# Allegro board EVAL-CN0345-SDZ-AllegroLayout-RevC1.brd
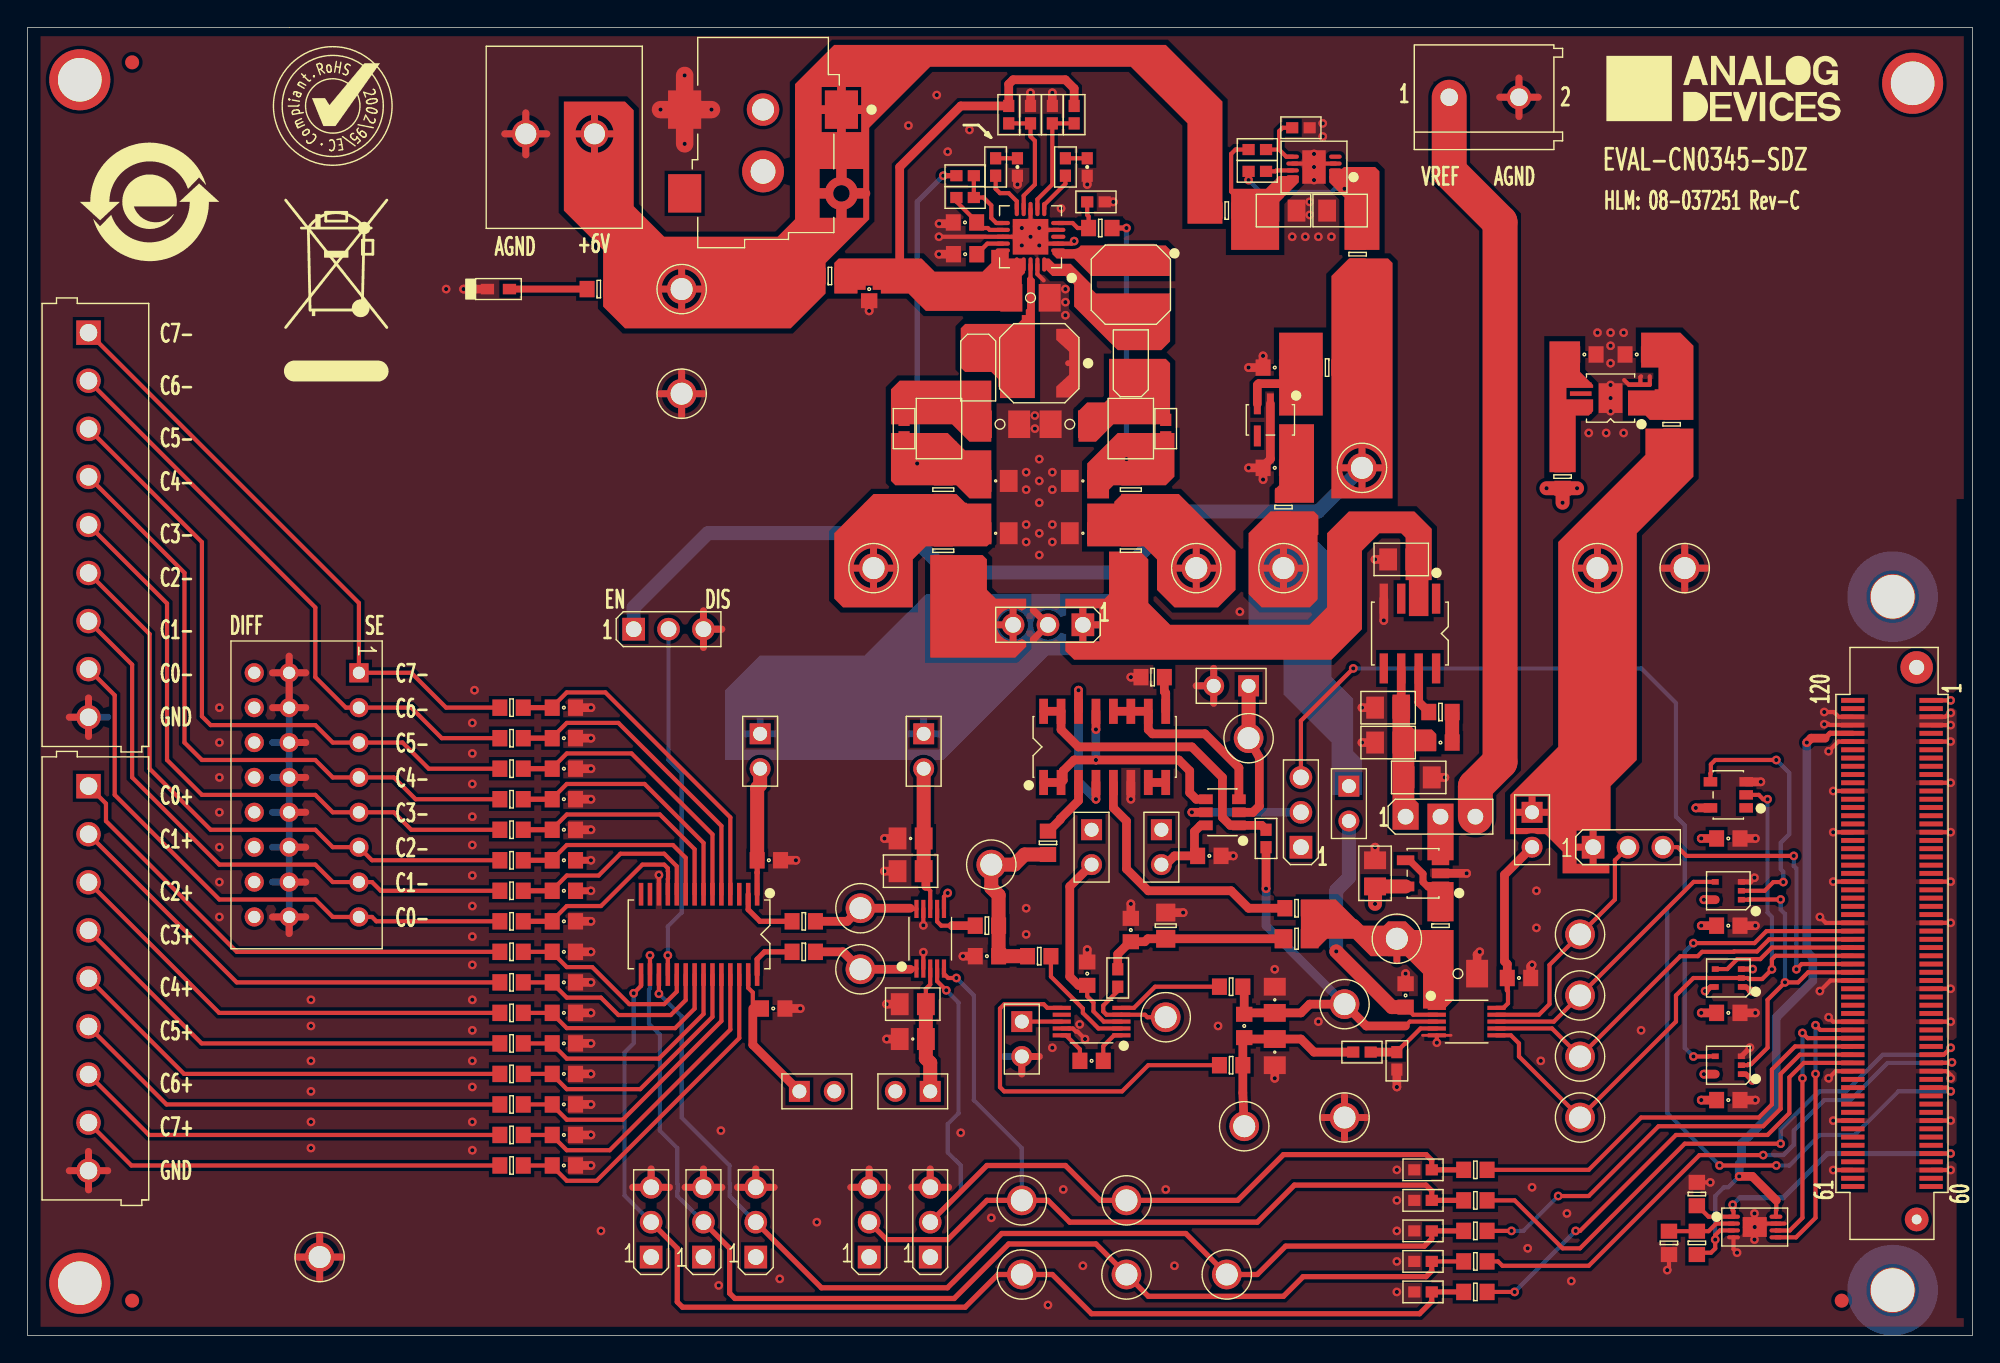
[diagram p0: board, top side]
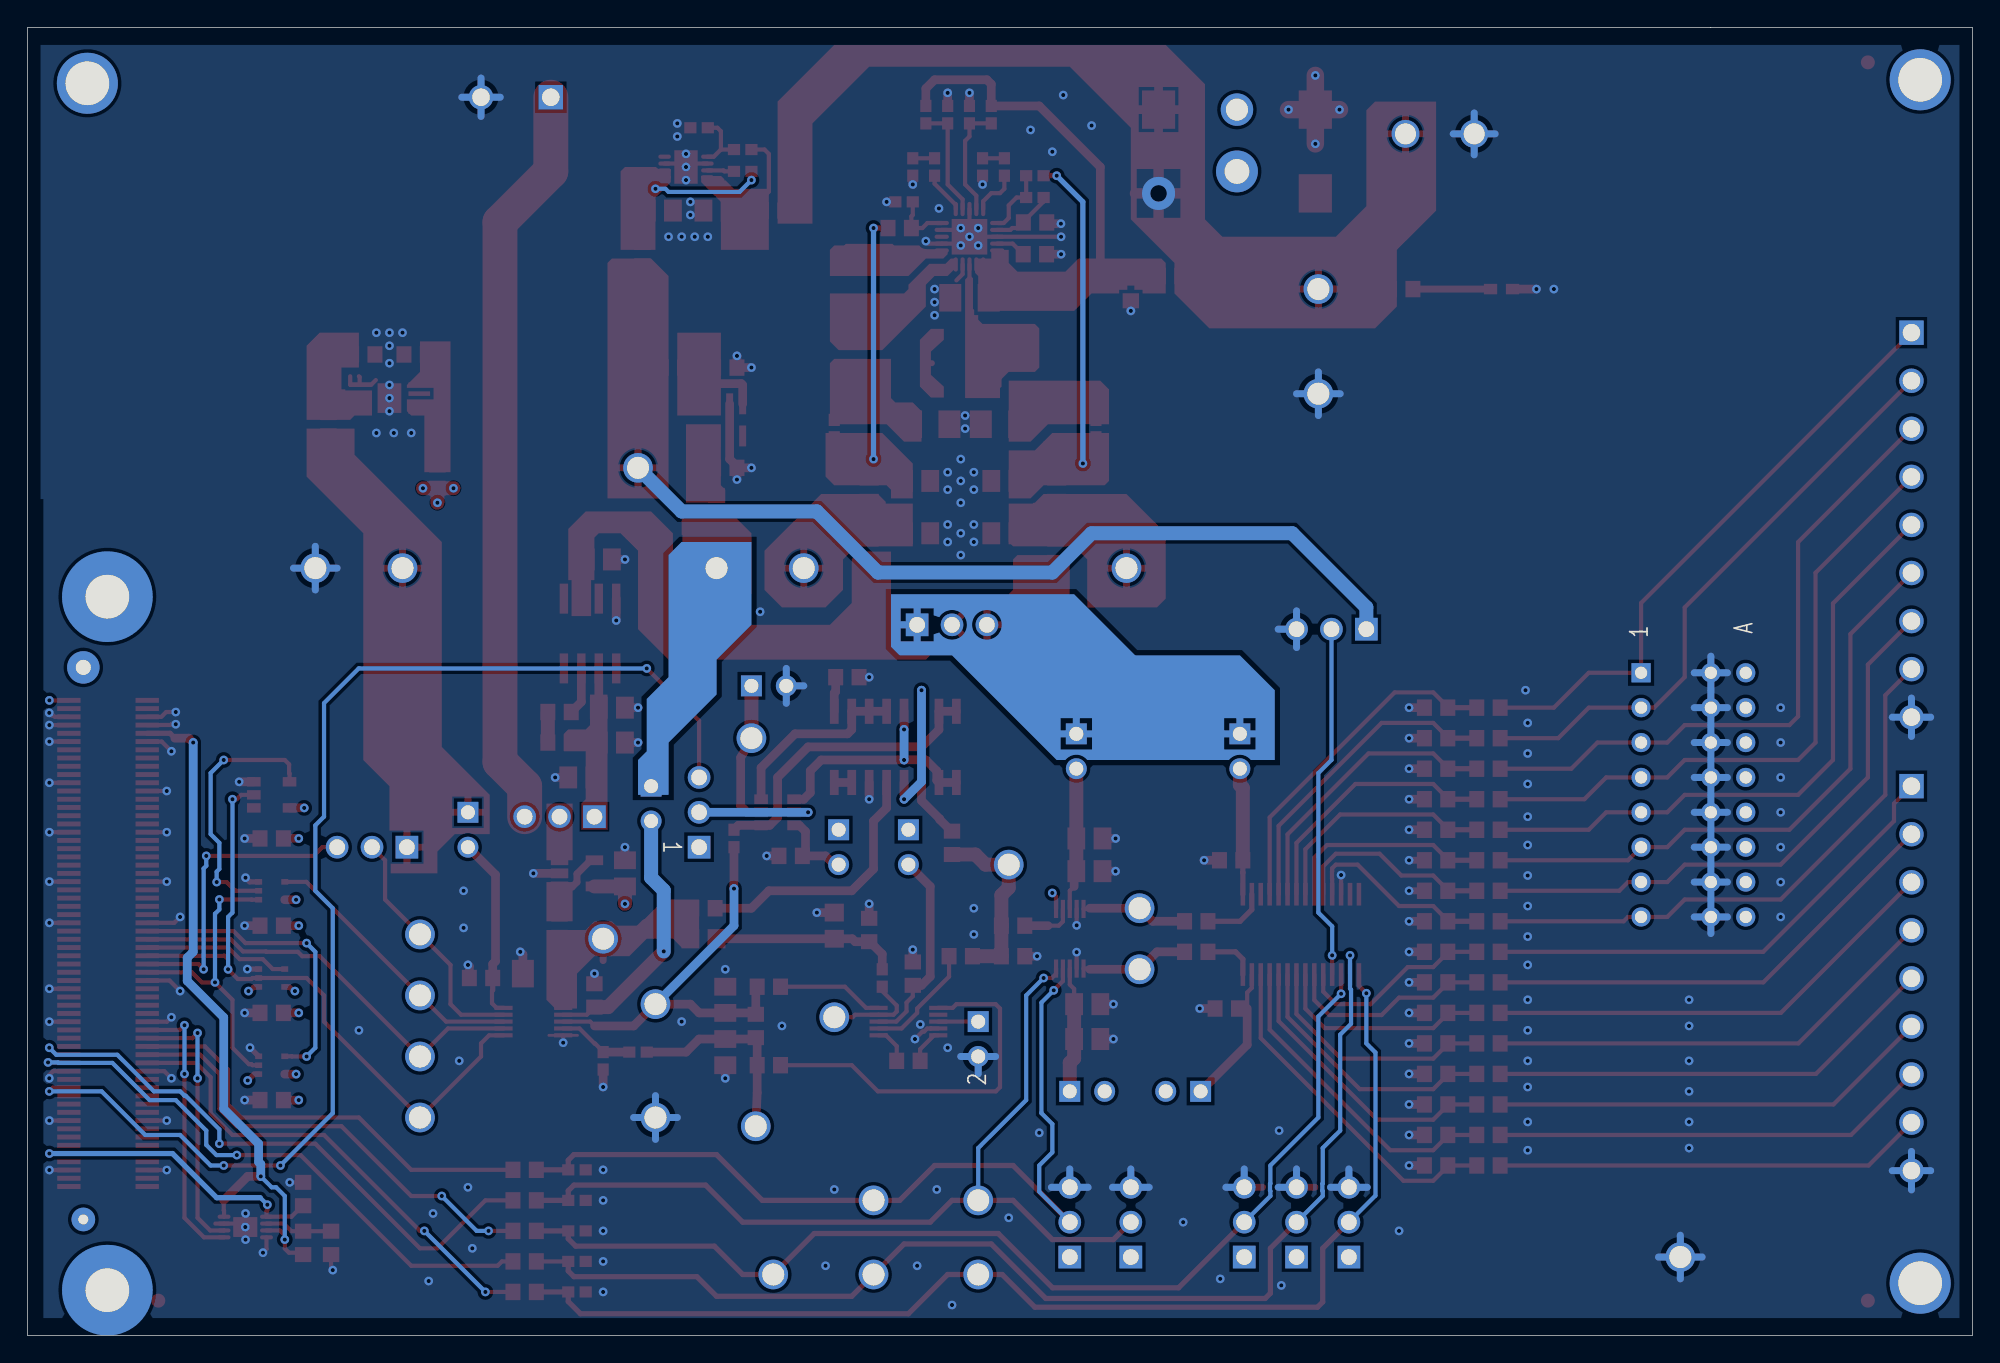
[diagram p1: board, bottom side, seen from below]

Outline 141.61 x 95.25 mm; copper layers: TOP, L2_GND, L3_POWER, BOTTOM. Coordinates in mm from the lower left corner of the outline.
Outline path: 0,95.25 19.05,95.25 141.61,95.25 141.61,0 0,0 0,95.25

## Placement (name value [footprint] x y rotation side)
C1  2700pF  [C0603]  39.05 45.72 180 top
C2  2700pF  [C0603]  39.05 43.5 180 top
C3  2700pF  [C0603]  39.05 41.27 180 top
C4  2700pF  [C0603]  39.05 39.05 180 top
C5  2700pF  [C0603]  39.05 36.83 180 top
C6  2700pF  [C0603]  39.05 34.61 180 top
C7  2700pF  [C0603]  39.05 32.38 180 top
C8  2700pF  [C0603]  39.05 30.16 180 top
C9  2700pF  [C0603]  39.05 27.94 180 top
C10  2700pF  [C0603]  39.05 25.72 180 top
C11  2700pF  [C0603]  39.05 23.49 180 top
C12  2700pF  [C0603]  39.05 21.27 180 top
C13  2700pF  [C0603]  39.05 19.05 180 top
C14  2700pF  [C0603]  39.05 16.83 180 top
C15  2700pF  [C0603]  39.05 14.61 180 top
C16  2700pF  [C0603]  39.05 12.38 180 top
C17  0.1UF  [C0603]  54.29 23.81 0 top
C18  0.1UF  [C0603]  53.98 34.61 0 top
C19  0.1uF  [C0805H53]  64.29 33.81 0 top
C20  10uF  [C0805H60]  64.29 36.2 0 top
C21  0.1UF  [C0603]  86.04 34.92 0 top
C22  10uF  [C0805H60]  64.45 21.59 180 top
C23  0.1uF  [C0805H53]  64.45 24.13 180 top
C24  2700pF  [C0603]  69.85 27.62 0 top
C25  2700pF  [C0603]  77.47 20 0 top
C26  0.1UF  [C0603]  77.15 26.35 270 top
C27  0.1uF  [C0603]  80.33 29.53 270 top
C28  1200pF  [C0805]  90.81 24.45 90 top
C29  1200pF  [C0805]  90.81 20.64 90 top
C30  1000PF  [C0603]  88.58 22.54 90 top
C31  10uF  [C1206H71]  104.14 26.35 180 top
C32  0.1UF  [C0603]  100.33 24.77 270 top
C33  0.1UF  [C0603]  108.59 26.04 0 top
C34  0.1uF  [C0805H53]  100.01 56.52 0 top
C35  22uF  [C0603]  61.28 76.2 90 top
C36  1uF  [C0603]  68.26 78.74 0 top
C37  10000pF  [C0603]  102.87 43.18 180 top
C38  10uF  [C1206H71]  73.03 75.57 180 top
C39  0.1uF  [C0805H53]  99.06 45.72 0 top
C40  1UF  [C0805H53]  99.06 43.18 0 top
C41  1UF  [C0805H53]  91.44 81.92 180 top
C42  0.1uF  [C0805H53]  101.28 40.64 180 top
C43  1uF  [C1206H71]  70.8 66.36 180 top
C44  1uF  [C1206H71]  75.88 66.36 0 top
C45  0.1uF  [C0805H53]  98.11 33.66 90 top
C46  6800pF  [C0402]  77.15 85.09 270 top
C47  39000pF  [C0402]  72.07 85.09 270 top
C48  1uF  [C0603]  68.25 81.05 180 top
C49  10uF  [C0805H60]  70.49 62.23 0 top
C50  10uF  [C0805H60]  76.84 62.23 0 top
C51  1UF  [C0805H53]  95.57 81.92 0 top
C52  10uF  [C0805H60]  76.84 58.42 0 top
C53  10uF  [C0805H60]  70.49 58.42 180 top
C54  1UF  [C0603]  90.81 70.48 0 top
C55  1UF  [C0603]  113.35 71.44 180 top
C56  1UF  [C0603]  90.81 63.18 0 top
C57  1UF  [C0603]  117.16 71.44 0 top
C58  0.1uF  [C0603]  123.83 29.84 180 top
C59  0.1uF  [C0603]  123.83 17.14 180 top
C60  0.1uF  [C0603]  123.83 36.2 180 top
C61  0.1uF  [C0603]  123.83 23.49 180 top
CNV  WHT  [CNLOOPTP]  113.03 15.88 0 top
D1  DFLS240-7  [DSML110W70H39]  80.33 70.8 90 top
D2  DFLS240-7  [DSML110W70H39]  69.22 70.48 270 top
DRV_IN  WHT  [CNLOOPTP]  70.17 34.29 0 top
GND1  BLK  [CNLOOPTP]  95.89 15.88 0 top
GND2  BLK  [CNLOOPTP]  120.65 55.88 0 top
GND3  BLK  [CNLOOPTP]  47.63 68.58 0 top
GND4  BLK  [CNLOOPTP]  21.27 5.71 0 top
IN+  WHT  [CNLOOPTP]  95.89 24.13 0 top
IN-  WHT  [CNLOOPTP]  88.58 15.24 0 top
L1  22uH  [LSMSQ189H123]  73.66 70.8 180 top
L2  22uH  [LSMSQ189H123]  80.33 76.52 270 top
L3  0.68uH  [LSML126W90H59]  66.36 66.04 270 top
L4  0.68uH  [LSML126W90H59]  80.33 66.04 270 top
MUX_0  WHT  [CNLOOPTP]  87.31 4.45 0 top
MUX_1  WHT  [CNLOOPTP]  80.01 4.45 0 top
MUX_2  WHT  [CNLOOPTP]  72.39 4.45 0 top
NOREF  -  []  -164.4 -183.78 0 top
NOREF#2  -  []  65.11 108.96 0 top
NOREF#3  -  []  -165.67 -185.05 0 top
NOREF#4  -  [unnamed#2]  7.62 92.71 180 top
NOREF#5  -  []  31.75 86.36 0 top
NOREF#6  -  []  123.51 90.81 0 top
NOREF#7  -  []  33.66 0 0 top
NOREF#8  -  [unnamed#2]  3.81 91.44 270 top
NOREF#9  -  [unnamed#2]  3.81 3.81 270 top
NOREF#10  -  []  141.69 76.2 180 top
NOREF#11  -  []  8.89 82.55 0 top
NOREF#12  -  [unnamed#2]  132.08 2.54 180 top
NOREF#13  -  []  -156.78 -174.63 0 top
NOREF#14  -  []  53.47 94.52 0 top
NOREF#15  -  []  208.75 320.17 0 top
NOREF#16  -  []  141.69 0 90 top
NOREF#17  -  []  33.66 76.2 270 top
NOREF#18  -  []  22.23 89.54 0 top
NOREF#19  -  [unnamed#2]  137.24 91.19 270 top
NOREF#20  -  []  174.97 92.45 0 top
NOREF#21  -  [unnamed#2]  7.62 2.54 180 top
NOREF#22  -  []  141.61 0 90 top
NOREF#23  -  []  10.16 307.34 0 top
NOREF#24  -  []  0 0 0 top
P1  CTB3051/9  [CNCELCTB3051_9]  4.45 73.03 270 top
P2  SAMTECTSW10608GS3PIN  [CNBERG1X3H205LD36]  100.33 37.78 0 top
P3  KRM2 02  [CNTERM_2P]  103.51 90.17 0 top
P4  SAMTECTSW10608GS3PIN  [CNBERG1X3H205LD36]  45.4 5.71 90 top
P5  SAMTECTSW10608GS3PIN  [CNBERG1X3H205LD36]  49.21 5.71 90 top
P6  SAMTECTSW10608GS3PIN  [CNBERG1X3H205LD36]  53.02 5.71 90 top
P7  69157-102  [CNBERG69157-102]  56.2 17.78 0 top
P8  69157-102  [CNBERG69157-102]  53.34 43.81 270 top
P9  SAMTECTSW10608GS3PIN  [CNBERG1X3H205LD36]  61.28 5.71 90 top
P10  SAMTECTSW10608GS3PIN  [CNBERG1X3H205LD36]  65.72 5.71 90 top
P11  69157-102  [CNBERG69157-102]  82.55 36.83 270 top
P12  69157-102  [CNBERG69157-102]  65.72 17.78 180 top
P13  69157-102  [CNBERG69157-102]  65.25 43.81 270 top
P14  69157-102  [CNBERG69157-102]  88.9 47.31 180 top
P15  69157-102  [CNBERG69157-102]  77.47 36.83 270 top
P16  69157-102  [CNBERG69157-102]  96.2 40.01 270 top
P17  69157-102  [CNBERG69157-102]  109.54 38.1 270 top
P18  SAMTECTSW10608GS3PIN  [CNBERG1X3H205LD36]  113.98 35.56 0 top
P19  PJ-002A-SMT  [CNCUI-PJ-002A]  53.55 86.87 180 top
P20  AK300/2 30.602  [CNALTECHAK300]  36.28 87.5 0 top
P21  SAMTECTSW10608GS3PIN  [CNBERG1X3H205LD36]  76.84 51.75 180 top
P22  FX8-120S-SV(21)  [CNHRSFX8-120S-SV_A]  135.74 28.55 270 top
P23  SAMTECTSW10608GS3PIN  [CNBERG1X3H205LD36]  92.71 35.56 90 top
P24  69157-102  [CNBERG69157-102]  72.39 22.86 270 top
P25  CTB3051/9  [CNCELCTB3051_9]  4.45 40.01 270 top
P26  SAMTECTSW10608GS3PIN  [CNBERG1X3H205LD36]  44.13 51.44 0 top
PGIA+  WHT  [CNLOOPTP]  60.64 31.11 0 top
PGIA-  WHT  [CNLOOPTP]  60.64 26.67 0 top
PGIA_0  WHT  [CNLOOPTP]  80.01 9.84 0 top
PGIA_1  WHT  [CNLOOPTP]  72.39 9.84 0 top
POWER  SML-310MTT86  [LED0603]  34.29 76.2 0 top
R1  0  [R0603]  35.24 45.72 0 top
R2  0  [R0603]  35.24 43.5 0 top
R3  0  [R0603]  35.24 41.27 0 top
R4  0  [R0603]  35.24 39.05 0 top
R5  0  [R0603]  35.24 36.83 0 top
R6  0  [R0603]  35.24 34.61 0 top
R7  0  [R0603]  35.24 32.38 0 top
R8  0  [R0603]  35.24 30.16 0 top
R9  0  [R0603]  35.24 27.94 0 top
R10  0  [R0603]  35.24 25.72 0 top
R11  0  [R0603]  35.24 23.49 0 top
R12  0  [R0603]  35.24 21.27 0 top
R13  0  [R0603]  35.24 19.05 0 top
R14  0  [R0603]  35.24 16.83 0 top
R15  0  [R0603]  35.24 14.61 0 top
R16  0  [R0603]  35.24 12.38 0 top
R17  0  [R0603]  105.41 3.17 0 top
R18  0  [R0603]  105.41 5.4 0 top
R19  0  [R0603]  105.41 7.62 0 top
R20  1K  [R0603]  74.3 35.88 90 top
R21  0  [R0603]  105.41 9.84 0 top
R22  0  [R0603]  105.41 12.07 0 top
R23  0  [R0603]  56.52 27.94 180 top
R24  0  [R0603]  56.52 30.16 180 top
R25  1K  [R0603]  81.92 47.94 0 top
R26  0  [R0603]  69.85 29.84 0 top
R27  10  [R0402]  90.17 36.2 270 top
R28  0  [R0603]  73.66 27.62 0 top
R29  0  [R0402]  97.16 20.64 0 top
R30  0  [R0402]  99.7 20 270 top
R31  10K  [R0805]  82.87 29.84 270 top
R32  10  [R0603]  87.63 25.4 0 top
R33  10  [R0603]  87.63 19.68 0 top
R34  10K  [R0805]  92.39 28.89 0 top
R35  2.1K  [R0603]  41.59 76.2 0 top
R36  0  [R0603]  58.42 77.15 0 top
R37  13.3K  [R0402]  74.61 88.9 270 top
R38  13.3K  [R0402]  73.03 88.9 270 top
R39  42.2K  [R0402]  76.2 88.9 270 top
R40  82K  [R0603]  102.87 45.4 0 top
R41  42.2K  [R0402]  71.44 88.9 90 top
R42  0  [R0603]  87.31 81.92 0 top
R43  100K  [R0402]  89.54 86.36 0 top
R44  3.57K  [R0402]  77.79 82.55 180 top
R45  374K  [R0402]  75.57 85.09 90 top
R46  80.6K  [R0402]  70.49 85.09 90 top
R47  2.8K  [R0402]  68.26 82.87 180 top
R48  100K  [R0402]  92.71 87.95 180 top
R49  54.9K  [R0402]  68.26 84.46 180 top
R50  11.5  [R0402]  63.82 66.04 270 top
R51  11.5  [R0402]  82.87 66.04 270 top
R52  63.4K  [R0603]  78.11 80.65 0 top
R53  0  [R0603]  102.87 29.84 270 top
R54  100K  [R0402]  89.54 84.77 0 top
R55  0  [R0603]  96.84 78.74 270 top
R56  0  [R0805]  80.33 61.59 270 top
R57  0  [R0805]  66.68 61.59 90 top
R58  0  [R0805]  80.33 57.15 270 top
R59  0  [R0805]  66.68 57.15 270 top
R60  0  [R0603]  94.62 70.48 180 top
R61  0  [R0603]  111.76 62.55 90 top
R62  0  [R0603]  91.44 60.32 270 top
R63  0  [R0603]  119.7 66.36 270 top
R64  100K  [R0603]  121.54 10.3 270 top
R65  100K  [R0603]  121.54 6.75 270 top
R66  100K  [R0603]  119.5 6.75 90 top
R67  0  [R0603]  92.39 31.11 0 top
R68  0  [R0402]  79.38 26.04 90 top
R69  10K  [R0402]  101.6 3.17 0 top
R70  10K  [R0402]  101.6 5.4 0 top
R71  10K  [R0402]  101.6 7.62 0 top
R72  10K  [R0402]  101.6 9.84 0 top
R73  10K  [R0402]  101.6 12.07 0 top
RN1  2K  [SO16NB-2]  78.42 42.86 0 top
S1  SCS 8-23  [SWTHL862W413H354]  24.13 48.26 270 top
SCLK  WHT  [CNLOOPTP]  113.03 24.77 0 top
SDI  WHT  [CNLOOPTP]  113.03 29.21 0 top
SDO  WHT  [CNLOOPTP]  113.03 20.32 0 top
U1  AD7982BRMZ  [RM10]  104.78 22.86 270 top
U2  ADG1207YRUZ  [TSSOP28]  48.9 29.21 180 top
U3  AD8251ARMZ  [RM10]  65.72 28.89 0 top
U4  ADA4805-1ARJZ  [SOT23_6-2]  87 38.1 90 top
U5  AD8475BRMZ  [RM10]  77.47 22.86 90 top
U6  ADP5070ACPZ  [QFN20_4X4_PAD2_6X2_6]  73.03 80.01 90 top
U7  ADP7104ACPZ-5.0  [QFN8_3X3_PAD2_44X1_7]  93.66 85.09 90 top
U8  ADR434BRZ  [SO8]  100.65 51.12 180 top
U9  AD8031ARTZ  [SOT23-M12]  101.6 33.66 90 top
U10  ADP124ARHZ-3.3-R7  [MSOP8_PAD2_16X1_73]  115.25 68.26 90 top
U11  ADP121-AUJZ25  [TSOT-5]  90.49 66.68 180 top
U12  24LC32A-I/MC  [DFN8_2X3_PAD1_45X1_75]  125.75 7.9 270 top
U13  NC7S04M5X  [SOT23-5P]  123.83 39.37 90 top
U14  NC7S08P5X  [SC70-5-2]  123.83 19.68 90 top
U15  NC7S08P5X  [SC70-5-2]  123.83 26.04 90 top
U16  NC7S08P5X  [SC70-5-2]  123.83 32.38 90 top
UNK2.5V  WHT  [CNLOOPTP]  91.44 55.88 0 top
UNK3.3V  WHT  [CNLOOPTP]  114.3 55.88 270 top
UNK5V  WHT  [CNLOOPTP]  97.16 63.18 180 top
UNK+15V  WHT  [CNLOOPTP]  85.09 55.88 90 top
UNK-15V  WHT  [CNLOOPTP]  61.6 55.88 90 top
UNK-VS  WHT  [CNLOOPTP]  88.9 43.5 0 top
VIN  WHT  [CNLOOPTP]  47.63 76.2 270 top
VOCM  WHT  [CNLOOPTP]  82.87 23.18 0 top
VREF  WHT  [CNLOOPTP]  99.7 28.89 0 top

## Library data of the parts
C1-C16 C24 C25 = CAP: Tolerance: 5; User Part Number: UPN; part number: CAP_SM-2700PF,50V,5,E011690,C0603; tolerance: 5
C17 C18 C21 C26 C32 C33 = CAP: Tolerance: 10; User Part Number: UPN; part number: CAP_SM-0.1UF,25V,10,E007204,C0603; tolerance: 10
C19 C23 C34 C39 C42 C45 = CAP: Tolerance: 10; User Part Number: UPN; part number: CAP_SM-0.1UF,50V,10,E010137,C0805H53; tolerance: 10
C20 C22 C49 C50 C52 C53 = CAP: Tolerance: 10; User Part Number: UPN; part number: CAP_SM-10UF,25V,10,E014704,C0805H60; tolerance: 10
C27 C58-C61 = CAP: Tolerance: 10; User Part Number: UPN; part number: CAP_SM-0.1UF,50V,10,E011865,C0603; tolerance: 10
C28 C29 = CAP: Tolerance: 5; User Part Number: UPN; part number: CAP_SM-1200PF,50V,5,E020258,C0805; tolerance: 5
C30 = CAP: Tolerance: 1; User Part Number: UPN; part number: CAP_SM-1000PF,50V,1,E024659,C0603; tolerance: 1
C31 = CAP: Tolerance: 10; User Part Number: UPN; part number: CAP_SM-10UF,50V,10,E013961,C1206H71; tolerance: 10
C35 = CAP: Tolerance: 20; User Part Number: UPN; part number: CAP_SM-22UF,10V,20,E022680,C0603; tolerance: 20
C36 C48 = CAP: Tolerance: 10; User Part Number: UPN; part number: CAP_SM-1UF,10V,10,E011783,C0603; tolerance: 10
C37 = CAP: Tolerance: 10; User Part Number: UPN; part number: CAP_SM-10000PF,50V,10,E018587,C0603; tolerance: 10
C38 = CAP: Tolerance: 10; User Part Number: UPN; part number: CAP_SM-10UF,25V,10,E022363,C1206H71; tolerance: 10
C40 C41 C51 = CAP: Tolerance: 10; User Part Number: UPN; part number: CAP_SM-1UF,50V,10,E007202,C0805H53; tolerance: 10
C43 C44 = CAP: Tolerance: 10; User Part Number: UPN; part number: CAP_SM-1UF,25V,10,E013038,C1206H71; tolerance: 10
C46 = CAP: Tolerance: 10; User Part Number: UPN; part number: CAP_SM-6800PF,25V,10,E012594,C0402; tolerance: 10
C47 = CAP: Tolerance: 5; User Part Number: UPN; part number: CAP_SM-39000PF,10V,5,E012589,C0402; tolerance: 5
C54-C57 = CAP: Tolerance: 10; User Part Number: UPN; part number: CAP_SM-1UF,25V,10,E006992,C0603; tolerance: 10
CNV DRV_IN IN+ IN- MUX_0-MUX_2 PGIA+ PGIA- PGIA_0 PGIA_1 SCLK SDI SDO UNK2.5V UNK3.3V UNK5V UNK+15V UNK-15V UNK-VS VIN VOCM VREF = CNTP1P: User Part Number: UPN; alternate symbols: (CNBANANA_ALT); part number: CNTP1P_TH-WHT,E000946,CNLOOPTP
D1 D2 = DIOSCHOTTKY: Tolerance: N/A; User Part Number: UPN; alternate symbols: (SOD882L_ALT); part number: DIOSCHOTTKY_SM-DFLS240-7,40V,N/A,E019969,DSML110W70H39; tolerance: N/A
GND1-GND4 = CNTP1P: User Part Number: UPN; alternate symbols: (CNBANANA_ALT); part number: CNTP1P_TH-BLK,E000948,CNLOOPTP
L1 L2 = IND: User Part Number: UPN; Tolerance: 20; alternate symbols: (L0402-2,L0603_ALT,L1008L_ALT); part number: IND_SM-22UH,20,E020360,LSMSQ189H123; tolerance: 20
L3 L4 = IND: User Part Number: UPN; Tolerance: 20; alternate symbols: (L0402-2,L0603_ALT,L1008L_ALT); part number: IND_SM-0.68UH,20,E020008,LSML126W90H59; tolerance: 20
P1 P25 = CN9P: User Part Number: UPN; part number: CN9P_TH-CTB3051/9,E008262,CNCELCTB3051_9
P2 P4-P6 P9 P10 P18 P21 P23 P26 = CN3P: User Part Number: UPN; part number: CN3P_TH-SAMTECTSW10608GS3PIN,E000812,CNBERG1X3H205LD36
P3 = CN2P: User Part Number: UPN; part number: CN2P_TH-KRM2 02,E000796,CNTERM_2P
P7 P8 P11-P17 P24 = CN2P: User Part Number: UPN; part number: CN2P_TH-69157-102,E000791,CNBERG69157-102
P19 = CN3P_V6: User Part Number: UPN; part number: CN3P_V6_SM-PJ-002A-SMT,E017261,CNCUI-PJ-002A
P20 = CN2P: User Part Number: UPN; part number: CN2P_TH-AK300/2 30.602,E012201,CNALTECHAK300
P22 = CN120P_V4: User Part Number: UPN; part number: CN120P_V4_SM-FX8-120S-SV(21),E016993,CNHRSFX8-120S-SV_A
POWER = DIOLED: User Part Number: UPN; Tolerance: N/A; part number: DIOLED_SM-SML-310MTT86,2.8V,N/A,E001179,LED0603; tolerance: N/A
R1-R19 R21-R24 R26 R28 R42 R53 R55 R60-R63 R67 = RES: Tolerance: 1; User Part Number: UPN; part number: RES_SM-0,E004207,1/16W,1,R0603; tolerance: 1
R20 R25 = RES: Tolerance: 1; User Part Number: UPN; part number: RES_SM-1K,E003678,1/10W,1,R0603; tolerance: 1
R27 = RES: Tolerance: 1; User Part Number: UPN; part number: RES_SM-10,E003768,1/16W,1,R0402; tolerance: 1
R29 R30 R68 = RES: Tolerance: 5; User Part Number: UPN; part number: RES_SM-0,E003438,1/16W,5,R0402; tolerance: 5
R31 R34 = RES: Tolerance: 0.1; User Part Number: UPN; part number: RES_SM-10K,E003806,1/8W,0.1,R0805; tolerance: 0.1
R32 R33 = RES: Tolerance: 1; User Part Number: UPN; part number: RES_SM-10,E003666,1/10W,1,R0603; tolerance: 1
R35 = RES: Tolerance: 1; User Part Number: UPN; part number: RES_SM-2.1K,E011132,1/10W,1,R0603; tolerance: 1
R36 = RES: Tolerance: 5; User Part Number: UPN; part number: RES_SM-0,E006826,1/10W,5,R0603; tolerance: 5
R37 R38 = RES: Tolerance: 1; User Part Number: UPN; part number: RES_SM-13.3K,E022434,1/10W,1,R0402; tolerance: 1
R39 R41 = RES: Tolerance: 1; User Part Number: UPN; part number: RES_SM-42.2K,E020077,1/10W,1,R0402; tolerance: 1
R40 = RES: Tolerance: 1; User Part Number: UPN; part number: RES_SM-82K,E004252,1/16W,1,R0603; tolerance: 1
R43 R48 R54 = RES: Tolerance: 5; User Part Number: UPN; part number: RES_SM-100K,E003464,1/10W,5,R0402; tolerance: 5
R44 = RES: Tolerance: 1; User Part Number: UPN; part number: RES_SM-3.57K,E007344,1/10W,1,R0402; tolerance: 1
R45 = RES: Tolerance: 1; User Part Number: UPN; part number: RES_SM-374K,E022652,1/10W,1,R0402; tolerance: 1
R46 = RES: Tolerance: 1; User Part Number: UPN; part number: RES_SM-80.6K,E006346,1/16W,1,R0402; tolerance: 1
R47 = RES: Tolerance: 1; User Part Number: UPN; part number: RES_SM-2.8K,E012202,1/10W,1,R0402; tolerance: 1
R49 = RES: Tolerance: 1; User Part Number: UPN; part number: RES_SM-54.9K,E023190,1/10W,1,R0402; tolerance: 1
R50 R51 = RES: Tolerance: 1; User Part Number: UPN; part number: RES_SM-11.5,E008013,1/16W,1,R0402; tolerance: 1
R52 = RES: Tolerance: 1; User Part Number: UPN; part number: RES_SM-63.4K,E006631,1/10W,1,R0603; tolerance: 1
R56-R59 = RES: Tolerance: 1; User Part Number: UPN; part number: RES_SM-0,E004152,1/10W,1,R0805; tolerance: 1
R64-R66 = RES: Tolerance: 1; User Part Number: UPN; part number: RES_SM-100K,E010279,1/10W,1,R0603; tolerance: 1
R69-R73 = RES: Tolerance: 5; User Part Number: UPN; part number: RES_SM-10K,E019640,1/16W,5,R0402; tolerance: 5
RN1 = RESNET_16P_8R: Tolerance: 0.1; User Part Number: UPN; part number: RESNET_16P_8R_SM-2K,E022975,1/10W,0.1,SO16NB-2; tolerance: 0.1
S1 = SWSPDT_24P: User Part Number: UPN; part number: SWSPDT_24P_TH-SCS 8-23,E017828,SWTHL862W413H354
U1 = AD7982_V2: User Part Number: UPN; part number: AD7982_V2_SM-AD7982BRMZ,E008107,RM10
U2 = ADG1207: User Part Number: UPN; part number: ADG1207_SM-ADG1207YRUZ,E006774,TSSOP28
U3 = AD8251: User Part Number: UPN; part number: AD8251_SM-AD8251ARMZ,E019018,RM10
U4 = ADA4805_1: User Part Number: UPN; part number: ADA4805_1_SM-ADA4805-1ARJZ,E018209,SOT23_6-2
U5 = AD8475_V2: User Part Number: UPN; part number: AD8475_V2_SM-AD8475BRMZ,E017389,RM10
U6 = ADP5070: User Part Number: UPN; part number: ADP5070_SM-ADP5070ACPZ,E017319,QFN20_4X4_PAD2_6X2_6
U7 = ADP7104: User Part Number: UPN; part number: ADP7104_SM-ADP7104ACPZ-5.0,E014913,QFN8_3X3_PAD2_44X1_7
U8 = ADR43X: User Part Number: UPN; part number: ADR43X_SM-ADR434BRZ,E022969,SO8
U9 = AD8541ART: User Part Number: UPN; part number: AD8541ART_SM-AD8031ARTZ,E005286,SOT23-M12
U10 = ADP124: User Part Number: UPN; part number: ADP124_SM-ADP124ARHZ-3.3-R7,E012626,MSOP8_PAD2_16X1_73
U11 = ADP121: User Part Number: UPN; part number: ADP121_SM-ADP121-AUJZ25,E013944,TSOT-5
U12 = IC24XX32A: User Part Number: UPN; part number: IC24XX32A_SM-24LC32A-I/MC,E014159,DFN8_2X3_PAD1_45X1_75
U13 = CMOSNC7S04: User Part Number: UPN; part number: CMOSNC7S04_SM-NC7S04M5X,E018028,SOT23-5P
U14-U16 = CMOSNC7S08: User Part Number: UPN; part number: CMOSNC7S08_SM-NC7S08P5X,E013952,SC70-5-2

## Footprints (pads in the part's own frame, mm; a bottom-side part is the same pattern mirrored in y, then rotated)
C0402
  rect 0.889x0.813 smd: 1(-0.635,0) 2(0.635,0)
C0603
  rect 1.092x1.194 smd: 1(-0.851,0) 2(0.851,0)
C0805
  rect 1.295x1.6 smd: 1(-0.953,0) 2(0.953,0)
C0805H53
  rect 1.295x1.6 smd: 1(-0.953,0) 2(0.953,0)
C0805H60
  rect 1.295x1.6 smd: 1(-0.953,0) 2(0.953,0)
C1206H71
  rect 1.6x2.007 smd: 1(-1.397,0) 2(1.397,0)
CNALTECHAK300
  round 2.032 hole 1.524: 1(0,0) 2(5,0)
CNBERG1X3H205LD36
  rect 1.651x1.651 hole 1.143: 1(0,0)
  round 1.651 hole 1.143: 2(2.54,0) 3(5.08,0)
CNBERG69157-102
  rect 1.524x1.524 hole 1.016: 1(0,0)
  round 1.524 hole 1.016: 2(2.54,0)
CNCELCTB3051_9
  rect 1.778x1.778 hole 1.27: 1(0,0)
  round 1.778 hole 1.27: 2(3.5,0) 3(7,0) 4(10.5,0) 5(14,0) 6(17.5,0) 7(21,0) 8(24.5,0) 9(28,0)
CNCUI-PJ-002A
  round 3.048 hole 1.803 unplated: (0,2.1)
  round 2.362 hole 1.6 unplated: (0,-2.4)
  rect 2.413x2.794 smd: 1(-5.707,-2.4) 2(5.707,-2.4) 3(5.707,3.7)
CNHRSFX8-120S-SV_A
  round 3.302 hole 3.175 unplated: (-25.25,0.05) (25.25,0.05)
  round 2.362 hole 1.092 unplated: (-20.1,1.8)
  round 1.727 hole 0.711 unplated: (20.1,1.8)
  rect 0.356x1.702 smd: 1(-17.7,2.851) 2(-17.1,2.851) 3(-16.5,2.851) 4(-15.9,2.851) 5(-15.3,2.851) 6(-14.7,2.851) 7(-14.1,2.851) 8(-13.5,2.851) 9(-12.9,2.851) 10(-12.3,2.851) 11(-11.7,2.851) 12(-11.1,2.851) 13(-10.5,2.851) 14(-9.9,2.851) 15(-9.3,2.851) 16(-8.7,2.851) 17(-8.1,2.851) 18(-7.5,2.851) 19(-6.9,2.851) 20(-6.3,2.851) 21(-5.7,2.851) 22(-5.1,2.851) 23(-4.5,2.851) 24(-3.9,2.851) 25(-3.3,2.851) 26(-2.7,2.851) 27(-2.1,2.851) 28(-1.5,2.851) 29(-0.9,2.851) 30(-0.3,2.851) 31(0.3,2.851) 32(0.9,2.851) 33(1.5,2.851) 34(2.1,2.851) 35(2.7,2.851) 36(3.3,2.851) 37(3.9,2.851) 38(4.5,2.851) 39(5.1,2.851) 40(5.7,2.851) 41(6.3,2.851) 42(6.9,2.851) 43(7.5,2.851) 44(8.1,2.851) 45(8.7,2.851) 46(9.3,2.851) 47(9.9,2.851) 48(10.5,2.851) 49(11.1,2.851) 50(11.7,2.851) 51(12.3,2.851) 52(12.9,2.851) 53(13.5,2.851) 54(14.1,2.851) 55(14.7,2.851) 56(15.3,2.851) 57(15.9,2.851) 58(16.5,2.851) 59(17.1,2.851) 60(17.7,2.851) 61(17.7,-2.851) 62(17.1,-2.851) 63(16.5,-2.851) 64(15.9,-2.851) 65(15.3,-2.851) 66(14.7,-2.851) 67(14.1,-2.851) 68(13.5,-2.851) 69(12.9,-2.851) 70(12.3,-2.851) 71(11.7,-2.851) 72(11.1,-2.851) 73(10.5,-2.851) 74(9.9,-2.851) 75(9.3,-2.851) 76(8.7,-2.851) 77(8.1,-2.851) 78(7.5,-2.851) 79(6.9,-2.851) 80(6.3,-2.851) 81(5.7,-2.851) 82(5.1,-2.851) 83(4.5,-2.851) 84(3.9,-2.851) 85(3.3,-2.851) 86(2.7,-2.851) 87(2.1,-2.851) 88(1.5,-2.851) 89(0.9,-2.851) 90(0.3,-2.851) 91(-0.3,-2.851) 92(-0.9,-2.851) 93(-1.5,-2.851) 94(-2.1,-2.851) 95(-2.7,-2.851) 96(-3.3,-2.851) 97(-3.9,-2.851) 98(-4.5,-2.851) 99(-5.1,-2.851) 100(-5.7,-2.851) 101(-6.3,-2.851) 102(-6.9,-2.851) 103(-7.5,-2.851) 104(-8.1,-2.851) 105(-8.7,-2.851) 106(-9.3,-2.851) 107(-9.9,-2.851) 108(-10.5,-2.851) 109(-11.1,-2.851) 110(-11.7,-2.851) 111(-12.3,-2.851) 112(-12.9,-2.851) 113(-13.5,-2.851) 114(-14.1,-2.851) 115(-14.7,-2.851) 116(-15.3,-2.851) 117(-15.9,-2.851) 118(-16.5,-2.851) 119(-17.1,-2.851) 120(-17.7,-2.851)
CNLOOPTP
  round 2.159 hole 1.6: 1(0,0)
CNTERM_2P
  rect 1.778x1.778 hole 1.27: 1(0,0)
  round 1.778 hole 1.27: 2(5.08,0)
DFN8_2X3_PAD1_45X1_75
  oval 0.305x0.94 smd: 1(-0.75,-1.545) 2(-0.25,-1.545) 3(0.25,-1.545) 4(0.75,-1.545) 5(0.75,1.545) 6(0.25,1.545) 7(-0.25,1.545) 8(-0.75,1.545)
  rect 1.448x1.753 smd: PAD(0,0)
DSML110W70H39
  rect 0.889x1.397 smd: A(1.605,0)
  rect 2.21x1.397 smd: C(-0.945,0)
LED0603
  rect 0.965x0.762 smd: A(0.8,0) C(-0.8,0)
LSML126W90H59
  rect 0.889x2.54 smd: 1(-1.372,0) 2(1.372,0)
LSMSQ189H123
  custom 0.435x0.435 smd: 1(-2.103,0) 2(2.103,0)
MSOP8_PAD2_16X1_73
  rect 0.33x1.575 smd: 1(-0.975,-2.171) 2(-0.325,-2.171) 3(0.325,-2.171) 4(0.975,-2.171) 5(0.975,2.171) 6(0.325,2.171) 7(-0.325,2.171) 8(-0.975,2.171)
  rect 2.159x1.727 smd: PAD(0,0)
QFN8_3X3_PAD2_44X1_7
  oval 0.305x0.914 smd: 1(-0.75,-1.557) 2(-0.25,-1.557) 3(0.25,-1.557) 4(0.75,-1.557) 5(0.75,1.557) 6(0.25,1.557) 7(-0.25,1.557) 8(-0.75,1.557)
  rect 2.438x1.702 smd: PAD(0,0)
QFN20_4X4_PAD2_6X2_6
  oval 0.305x1.041 smd: 1(-1,-2.019) 2(-0.5,-2.019) 3(0,-2.019) 4(0.5,-2.019) 5(1,-2.019) 11(1,2.019) 12(0.5,2.019) 13(0,2.019) 14(-0.5,2.019) 15(-1,2.019)
  oval 1.041x0.305 smd: 6(2.019,-1) 7(2.019,-0.5) 8(2.019,0) 9(2.019,0.5) 10(2.019,1) 16(-2.019,1) 17(-2.019,0.5) 18(-2.019,0) 19(-2.019,-0.5) 20(-2.019,-1)
  rect 2.591x2.591 smd: PAD(0,0)
R0402
  rect 0.889x0.813 smd: 1(-0.635,0) 2(0.635,0)
R0603
  rect 1.092x1.194 smd: 1(-0.851,0) 2(0.851,0)
R0805
  rect 1.295x1.397 smd: 1(-0.953,0) 2(0.953,0)
RM10
  rect 0.305x1.321 smd: 1(-1,-2.171) 2(-0.5,-2.171) 3(0,-2.171) 4(0.5,-2.171) 5(1,-2.171) 6(1,2.171) 7(0.5,2.171) 8(0,2.171) 9(-0.5,2.171) 10(-1,2.171)
SC70-5-2
  rect 0.406x0.508 smd: 1(-0.65,-0.95) 2(0,-0.95) 3(0.65,-0.95) 4(0.65,0.95) 5(-0.65,0.95)
SO8
  rect 0.61x2.184 smd: 1(-1.905,-2.54) 2(-0.635,-2.54) 3(0.635,-2.54) 4(1.905,-2.54) 5(1.905,2.54) 6(0.635,2.54) 7(-0.635,2.54) 8(-1.905,2.54)
SO16NB-2
  rect 0.635x1.829 smd: 1(-4.445,-2.591) 2(-3.175,-2.591) 3(-1.905,-2.591) 4(-0.635,-2.591) 5(0.635,-2.591) 6(1.905,-2.591) 7(3.175,-2.591) 8(4.445,-2.591) 9(4.445,2.591) 10(3.175,2.591) 11(1.905,2.591) 12(0.635,2.591) 13(-0.635,2.591) 14(-1.905,2.591) 15(-3.175,2.591) 16(-4.445,2.591)
SOT23-5P
  rect 0.686x0.991 smd: 1(-0.95,-1.3) 2(0,-1.3) 3(0.95,-1.3) 4(0.95,1.3) 5(-0.95,1.3)
SOT23-M12
  rect 0.711x1.27 smd: 1(-0.953,-1.27) 2(0,-1.27) 3(0.953,-1.27) 4(0.953,1.27) 5(-0.953,1.27)
SOT23_6-2
  rect 0.711x0.991 smd: 1(-0.95,-1.2) 2(0,-1.2) 3(0.95,-1.2) 4(0.95,1.2) 5(0,1.2) 6(-0.95,1.2)
SWTHL862W413H354
  rect 1.397x1.397 hole 0.889: 1(0,0)
  round 1.397 hole 0.889: 1A(0,-5.08) 2(2.54,0) 2B(2.54,-5.08) 3(5.08,0) 3C(5.08,-5.08) 4(7.62,0) 4D(7.62,-5.08) 5(10.16,0) 5E(10.16,-5.08) 6(12.7,0) 6F(12.7,-5.08) 7(15.24,0) 7G(15.24,-5.08) 8(17.78,0) 8H(17.78,-5.08) A(0,-7.62) B(2.54,-7.62) C(5.08,-7.62) D(7.62,-7.62) E(10.16,-7.62) F(12.7,-7.62) G(15.24,-7.62) H(17.78,-7.62)
TSOT-5
  rect 0.508x1.524 smd: 1(-0.95,-1.17) 2(0,-1.17) 3(0.95,-1.17) 4(0.95,1.17) 5(-0.95,1.17)
TSSOP28
  rect 0.33x1.651 smd: 1(-4.225,-2.925) 2(-3.575,-2.925) 3(-2.925,-2.925) 4(-2.275,-2.925) 5(-1.625,-2.925) 6(-0.975,-2.925) 7(-0.325,-2.925) 8(0.325,-2.925) 9(0.975,-2.925) 10(1.625,-2.925) 11(2.275,-2.925) 12(2.925,-2.925) 13(3.575,-2.925) 14(4.225,-2.925) 15(4.225,2.925) 16(3.575,2.925) 17(2.925,2.925) 18(2.275,2.925) 19(1.625,2.925) 20(0.975,2.925) 21(0.325,2.925) 22(-0.325,2.925) 23(-0.975,2.925) 24(-1.625,2.925) 25(-2.275,2.925) 26(-2.925,2.925) 27(-3.575,2.925) 28(-4.225,2.925)
unnamed#2
  round 1.016 smd: (0,0)

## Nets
2.5VA: P16.1(N1) R62.2(N2) UNK2.5V.1
5VA: C45.1(N1) P11.1(N1) P15.1(N1) P22.1(VIN) P23.1(N1) P26.1(N1) R55.2(N2) R60.1(N1) R61.1(N1) U9.5(V+) UNK5V.1
AGND: C1.1(N1) C2.1(N1) C3.1(N1) C4.1(N1) C5.1(N1) C6.1(N1) C7.1(N1) C8.1(N1) C9.1(N1) C10.1(N1) C11.1(N1) C12.1(N1) C13.1(N1) C14.1(N1) C15.1(N1) C16.1(N1) C17.2(N2) C18.2(N2) C19.1(N1) C20.1(N1) C21.2(N2) C22.2(N2) C23.2(N2) C24.1(N1) C26.1(N1) C27.1(N1) C28.2(N2) C29.1(N1) C31.1(N1) C32.1(N1) C33.2(N2) C34.1(N1) C35.1(N1) C36.1(N1) C38.1(N1) C39.1(N1) C40.1(N1) C41.1(N1) C42.1(N1) C43.1(N1) C44.1(N1) C45.2(N2) C46.2(N2) C47.2(N2) C48.2(N2) C49.2(N2) C50.1(N1) C51.1(N1) C52.1(N1) C53.1(N1) C54.1(N1) C55.1(N1) C56.1(N1) C57.1(N1) C58.1(N1) C59.1(N1) C60.1(N1) C61.1(N1) GND1.1(N1) GND2.1(N1) GND3.1(N1) GND4.1(N1) L1.1(N1) P1.9(N9) P3.2(N2) P4.3(N3) P5.3(N3) P6.3(N3) P9.3(N3) P10.3(N3) P14.2(N2) P19.2(N2) P20.1(N1) P21.2(N2) P22.3(GND1) P22.4(GND2) P22.6(GND3) P22.11(GND4) P22.17(GND5) P22.23(GND6) P22.28(GND7) P22.36(GND8) P22.40(GND9) P22.46(GND10) P22.52(GND11) P22.58(GND12) P22.63(GND13) P22.69(GND14) P22.75(GND15) P22.81(GND16) P22.86(GND17) P22.93(GND18) P22.98(GND19) P22.104(GND20) P22.109(GND21) P22.115(GND22) P22.117(GND23) P22.118(GND24) P24.2(N2) P25.9(N9) P26.3(N3) POWER.C(N) R25.1(N1) R30.2(N2) R31.1(N1) R37.1(N1) R38.1(N1) R44.1(N1) R48.1(N1) R64.1(N1) R66.1(N1) R69.1(N1) R70.1(N1) R71.1(N1) R72.1(N1) R73.1(N1) RN1.6(N1) S1.1A(C1) S1.2B(C2) S1.3C(C3) S1.4D(C4) S1.5E(C5) S1.6F(C6) S1.7G(C7) S1.8H(C8) U1.5(GND) U2.12(GND) U3.2(DGND) U3.9(REF) U5.9(POS_IN0_4X) U6.2(SYNC/FREQ) U6.4(SLEW) U6.8(SS) U6.13(AGND) U6.19(PGND) U6.PAD U7.3(GND1) U7.6(GND2) U7.PAD U8.4(GND) U9.2(V-) U10.4(GND) U10.PAD(EP) U11.2(GND) U12.4(VSS) U12.7(WP) U12.PAD U13.3(GND) U14.3(GND) U15.3(GND) U16.3(GND)
P15VA: C34.2(N2) P8.1(N1) P13.1(N1) P21.1(N1) R58.2(N2) U8.2(VIN)
VIN: P19.1(N1) P20.2(N2) R35.2(N2) R36.1(N1) R42.1(N1) VIN.1(N1)
3P3V: C58.2(N2) C59.2(N2) C60.2(N2) C61.2(N2) P4.1(N1) P5.1(N1) P6.1(N1) P9.1(N1) P10.1(N1) P17.1(N1) P18.1(N1) R63.2(N2) U13.5(VCC) U14.1(A) U14.5(VCC) U15.1(A) U15.5(VCC) U16.5(VCC) UNK3.3V.1
AMP_ADDR0: P10.2(N2) PGIA_0.1(N1) R22.1(N1) R73.2(N2) U3.4(A0)
AMP_ADDR1: P9.2(N2) PGIA_1.1(N1) R21.1(N1) R72.2(N2) U3.5(A1)
BUFF_IN: C24.2(N2) DRV_IN.1(N1) R20.1(N1) R26.2(N2) R28.1(N1)
CNV: CNV.1(N1) P22.89(SPORT_TFS) U1.6(CNV) U13.2(A) U15.2(B)
GPIO1: P22.78(GPIO1) R22.2(N2)
GPIO2: P22.44(GPIO2) R21.2(N2)
GPIO3: P22.77(GPIO3) R19.2(N2)
GPIO4: P22.45(GPIO4) R18.2(N2)
GPIO5: P22.76(GPIO5) R17.2(N2)
IN0A: C9.2(N2) R9.2(N2) U2.19(S1A)
IN0B: C8.2(N2) R8.2(N2) U2.11(S1B)
IN1A: C10.2(N2) R10.2(N2) U2.20(S2A)
IN1B: C7.2(N2) R7.2(N2) U2.10(S2B)
IN2A: C11.2(N2) R11.2(N2) U2.21(S3A)
IN2B: C6.2(N2) R6.2(N2) U2.9(S3B)
IN3A: C12.2(N2) R12.2(N2) U2.22(S4A)
IN3B: C5.2(N2) R5.2(N2) U2.8(S4B)
IN4A: C13.2(N2) R13.2(N2) U2.23(S5A)
IN4B: C4.2(N2) R4.2(N2) U2.7(S5B)
IN5A: C14.2(N2) R14.2(N2) U2.24(S6A)
IN5B: C3.2(N2) R3.2(N2) U2.6(S6B)
IN6A: C15.2(N2) R15.2(N2) U2.25(S7A)
IN6B: C2.2(N2) R2.2(N2) U2.5(S7B)
IN7A: C16.2(N2) R16.2(N2) U2.26(S8A)
IN7B: C1.2(N2) R1.2(N2) U2.4(S8B)
IN+: C28.1(N1) C30.2(N2) IN+.1(N1) R27.2(N2) R32.2(N2) U1.3(IN_POS)
IN-: C29.2(N2) C30.1(N1) IN-.1(N1) R29.1(N1) R33.2(N2)
MUX_ADDR0: MUX_0.1(N1) P6.2(N2) R19.1(N1) R71.2(N2) U2.17(A0)
MUX_ADDR1: MUX_1.1(N1) P5.2(N2) R18.1(N1) R70.2(N2) U2.16(A1)
MUX_ADDR2: MUX_2.1(N1) P4.2(N2) R17.1(N1) R69.2(N2) U2.15(A2)
MUX_EN: P26.2(N2) U2.18(EN)
N15VA: P7.2(N2) P12.2(N2) P21.3(N3) R59.2(N2) U3.6(WR_N)
PD: P22.48(TMR_A) P23.3(N3)
SCLK: SCLK.1(N1) U1.8(SCK) U16.4(Y)
SDI: P18.2(N2) SDI.1(N1) U1.9(SDI)
SDO: P22.91(SPORT_DR0) SDO.1(N1) U1.7(SDO)
SDP_3P3V: P22.116(VIO(+3.3V)) R65.2(N2) U12.3(A2) U12.8(VCC)
SPORT_DT0: P18.3(N3) P22.88(SPORT_DT0)
SPORT_RFS: P22.90(SPORT_RFS) U15.4(Y)
SPORT_RSCLK: P22.92(SPORT_RSCLK) U14.4(Y)
SPORT_TSCLK: P22.87(SPORT_TSCLK) U14.2(B) U16.1(A)
SW0: P1.8(N8) R8.1(N1) S1.8(NO8)
SW1: P1.7(N7) R7.1(N1) S1.7(NO7)
SW2: P1.6(N6) R6.1(N1) S1.6(NO6)
SW3: P1.5(N5) R5.1(N1) S1.5(NO5)
SW4: P1.4(N4) R4.1(N1) S1.4(NO4)
SW5: P1.3(N3) R3.1(N1) S1.3(NO3)
SW6: P1.2(N2) R2.1(N1) S1.2(NO2)
SW7: P1.1(N1) R1.1(N1) S1.1(NO1)
UNNAMED_1_AD7982V2_I124_INNEG: R29.2(N2) R30.1(N1) U1.4(IN_NEG)
UNNAMED_1_AD7982V2_I124_VDD: C32.2(N2) P16.2(N2) U1.2(VDD)
UNNAMED_1_AD7982V2_I124_VIO: C33.1(N1) P17.2(N2) U1.10(VIO)
UNNAMED_1_AD8251_I135_: PGIA-.1(N1) R23.1(N1) U3.1(-IN)
UNNAMED_1_AD8251_I135__1: PGIA+.1(N1) R24.1(N1) U3.10(+IN)
UNNAMED_1_AD8251_I135__2: C22.1(N1) C23.1(N1) P12.1(N1) U3.3(-VS)
UNNAMED_1_AD8251_I135__3: C19.2(N2) C20.2(N2) P13.2(N2) U3.8(+VS)
UNNAMED_1_AD8251_I135_OUT: R26.1(N1) U3.7(OUT)
UNNAMED_1_AD8475V2_I91_NEGIN04X: R28.2(N2) U5.2(NEG_IN0_4X)
UNNAMED_1_AD8475V2_I91_NEGIN08X: C25.2(N2) U5.1(NEG_IN0_8X)
UNNAMED_1_AD8475V2_I91_NEGVS: P24.1(N1) U5.8(NEG_VS)
UNNAMED_1_AD8475V2_I91_POSIN08X: C25.1(N1) U5.10(POS_IN0_8X)
UNNAMED_1_AD8475V2_I91_POSVS: C26.2(N2) P15.2(N2) U5.3(POS_VS)
UNNAMED_1_AD8475V2_I91_VOCM: R68.1(N1) U5.4(VOCM) VOCM.1(N1)
UNNAMED_1_ADA48051_I112_: RN1.1(N1) RN1.2(N1) RN1.13(N2) U4.4(-IN)
UNNAMED_1_ADA48051_I112__1: RN1.10(N2) RN1.11(N2) RN1.12(N2) U4.3(+IN)
UNNAMED_1_ADA48051_I112__2: P14.1(N1) U4.2(-VS) UNK-VS.1
UNNAMED_1_ADA48051_I112__3: C21.1(N1) P11.2(N2) U4.6(+VS)
UNNAMED_1_ADA48051_I112_DISABLE: P23.2(N2) U4.5(DISABLE_N)
UNNAMED_1_ADA48051_I112_VOUT: R27.1(N1) RN1.15(N2) RN1.16(N2) U4.1(VOUT)
UNNAMED_1_ADG1207_I45_DA: R23.2(N2) U2.28(DA)
UNNAMED_1_ADG1207_I45_DB: R24.2(N2) U2.2(DB)
UNNAMED_1_ADG1207_I45_VDD: C18.1(N1) P8.2(N2) U2.1(VDD)
UNNAMED_1_ADG1207_I45_VSS: C17.1(N1) P7.1(N1) U2.27(VSS)
UNNAMED_1_CAP_I95_N2: C27.2(N2) R31.2(N2) R34.1(N1) R68.2(N2)
UNNAMED_1_CN9P_I241_N1: P25.1(N1) R9.1(N1)
UNNAMED_1_CN9P_I241_N2: P25.2(N2) R10.1(N1)
UNNAMED_1_CN9P_I241_N3: P25.3(N3) R11.1(N1)
UNNAMED_1_CN9P_I241_N4: P25.4(N4) R12.1(N1)
UNNAMED_1_CN9P_I241_N5: P25.5(N5) R13.1(N1)
UNNAMED_1_CN9P_I241_N6: P25.6(N6) R14.1(N1)
UNNAMED_1_CN9P_I241_N7: P25.7(N7) R15.1(N1)
UNNAMED_1_CN9P_I241_N8: P25.8(N8) R16.1(N1)
UNNAMED_1_RES_I104_N1: R33.1(N1) U5.6(NEG_OUT)
UNNAMED_1_RES_I109_N1: R32.1(N1) U5.5(POS_OUT)
UNNAMED_1_RES_I214_N2: R20.2(N2) RN1.3(N1)
UNNAMED_1_RES_I215_N2: R25.2(N2) RN1.9(N2)
UNNAMED_1_RES_I218_N1: R67.1(N1) RN1.5(N1)
UNNAMED_1_RESNET16P8R_I207_N1: RN1.7(N1) RN1.8(N1)
UNNAMED_1_RESNET16P8R_I208_N1: RN1.4(N1) RN1.14(N2)
UNNAMED_2_AD8541ART_I251_: P2.2(N2) U9.3(+IN)
UNNAMED_2_AD8541ART_I251__1: R53.1(N1) U9.1(OUT) U9.4(-IN)
UNNAMED_2_ADP121_I85_EN: C54.2(N2) R60.2(N2) U11.1(VIN) U11.3(EN)
UNNAMED_2_ADP121_I85_VOUT: C56.2(N2) R62.1(N1) U11.5(VOUT)
UNNAMED_2_ADP124_I107_EN: C55.2(N2) R61.2(N2) U10.5(EN) U10.7(VIN1) U10.8(VIN2)
UNNAMED_2_ADP124_I107_VOUT1: C57.2(N2) R63.1(N1) U10.1(VOUT1) U10.2(VOUT2) U10.3(VOUT_SENSE)
UNNAMED_2_ADP5070_I245_COMP1: R45.1(N1) U6.6(COMP1)
UNNAMED_2_ADP5070_I245_COMP2: R46.1(N1) U6.10(COMP2)
UNNAMED_2_ADP5070_I245_EN1: R37.2(N2) R39.2(N2) U6.7(EN1)
UNNAMED_2_ADP5070_I245_EN2: R38.2(N2) R41.1(N1) U6.9(EN2)
UNNAMED_2_ADP5070_I245_FB1: R44.2(N2) R52.1(N1) U6.5(FB1)
UNNAMED_2_ADP5070_I245_FB2: R47.1(N1) R49.1(N1) U6.11(FB2)
UNNAMED_2_ADP5070_I245_INBK: L2.1(N1) U6.1(INBK)
UNNAMED_2_ADP5070_I245_PVIN1: C35.2(N2) C38.2(N2) R36.2(N2) R39.1(N1) R41.2(N2) U6.15(PVIN1) U6.16(PVINSYS) U6.17(PVIN2)
UNNAMED_2_ADP5070_I245_SW1: D1.A(P) L2.2(N2) U6.20(SW1)
UNNAMED_2_ADP5070_I245_SW2: D2.C(N) L1.2(N2) U6.18(SW2)
UNNAMED_2_ADP5070_I245_VREF: C48.1(N1) R47.2(N2) U6.12(VREF)
UNNAMED_2_ADP5070_I245_VREG: C36.2(N2) U6.14(VREG)
UNNAMED_2_ADP7104_I106_EN: R43.2(N2) R48.2(N2) U7.5(EN)
UNNAMED_2_ADP7104_I106_PG: R54.2(N2) U7.7(PG)
UNNAMED_2_ADP7104_I106_SENSE: C51.2(N2) R54.1(N1) R55.1(N1) U7.1(VOUT) U7.2(SENSE)
UNNAMED_2_ADP7104_I106_VIN: C41.2(N2) R42.2(N2) R43.1(N1) U7.8(VIN)
UNNAMED_2_ADR43X_I253_COMP: R40.1(N1) U8.7(COMP)
UNNAMED_2_ADR43X_I253_VOUT: C37.2(N2) C39.2(N2) C40.2(N2) C42.2(N2) P2.1(N1) U8.6(VOUT)
UNNAMED_2_CAP_I115_N1: C37.1(N1) R40.2(N2)
UNNAMED_2_CAP_I214_N2: C44.2(N2) D1.C(N) L4.1(N1) R51.1(N1)
UNNAMED_2_CAP_I216_N2: C50.2(N2) L4.2(N2) R51.2(N2) R52.2(N2) R56.1(N1)
UNNAMED_2_CAP_I221_N1: C46.1(N1) R45.2(N2)
UNNAMED_2_CAP_I228_N1: C49.1(N1) L3.2(N2) R49.2(N2) R50.2(N2) R57.2(N2)
UNNAMED_2_CAP_I234_N1: C47.1(N1) R46.2(N2)
UNNAMED_2_CAP_I257_N2: C52.2(N2) R56.2(N2) R58.1(N1) UNK+15V.1
UNNAMED_2_CAP_I258_N2: C53.2(N2) R57.1(N1) R59.1(N1) UNK-15V.1
UNNAMED_2_CAP_I264_N2: C43.2(N2) D2.A(P) L3.1(N1) R50.1(N1)
UNNAMED_2_CN2P_I119_N1: P2.3(N3) P3.1(N1)
UNNAMED_2_DIOLED_I248_P: POWER.A(P) R35.1(N1)
UNNAMED_3_CMOSNC7S04_I15_Y: U13.4(Y) U16.2(B)
UNNAMED_3_CN120PV4_I1_EEPROMA0: P22.56(EEPROM_A0) R64.2(N2) U12.1(A0)
UNNAMED_3_CN120PV4_I1_SCL0: P22.79(SCL_0) U12.6(SCL)
UNNAMED_3_CN120PV4_I1_SDA0: P22.80(SDA_0) U12.5(SDA)
UNNAMED_3_IC24XX32A_I2_A1: R65.1(N1) R66.2(N2) U12.2(A1)
VREF: C31.2(N2) R34.2(N2) R53.2(N2) R67.2(N2) U1.1(REF) VREF.1(N1)

Pads without a net: P19 3; P22 2 5 7 8 9 10 12 13 14 15 16 18 19 20 21 22 24 25 26 27 29 30 31 32 33 34 35 37 38 39 41 42 43 47 49 50 51 53 54 55 57 59 60 61 62 64 65 66 67 68 70 71 72 73 74 82 83 84 85 94 95 96 97 99 100 101 102 103 105 106 107 108 110 111 112 113 114 119 120; S1 A B C D E F G H; U2 3 13 14; U5 7; U6 3; U7 4; U8 1 3 5 8; U10 6; U11 4; U13 1

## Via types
v1: diameter 0.635, hole 0.305, TOP to BOTTOM, 282 vias
v2: diameter 2.413, hole 1.206, TOP to BOTTOM, 1 via

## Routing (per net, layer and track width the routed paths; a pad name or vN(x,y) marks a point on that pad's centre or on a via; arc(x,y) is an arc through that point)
2.5VA: length 6.4
  TOP w0.508: UNK2.5V.1 91.44,57.47 ; UNK2.5V.1 91.44,54.29 ; UNK2.5V.1 93.03,55.88 ; UNK2.5V.1 89.85,55.88
5VA: length 93.7
  TOP w0.305: P22.1 v1(140.01,46.25)
  TOP w0.508: 95.57,63.18 UNK5V.1 ; UNK5V.1 97.16,61.59 ; UNK5V.1 97.16,64.77 ; UNK5V.1 98.74,63.18
  TOP w1.016: R61.1 v1(111.76,60.64) ; R61.1 v1(110.59,61.7) ; R61.1 v1(112.81,61.7) ; v1(98.11,31.43) C45.1 U9.5
  L3_POWER w0.508: UNK5V.1 98.74,63.18 ; UNK5V.1 97.16,64.77 ; UNK5V.1 95.57,63.18 ; UNK5V.1 97.16,61.59 ; 92.71,34.23 P23.1 ; P23.1 91.38,35.56 ; P23.1 94.04,35.56 ; 76.2,36.83 P15.1 ; P15.1 78.74,36.83 ; P15.1 77.47,38.1 ; P11.1 83.82,36.83 ; P11.1 82.55,38.1 ; P11.1 81.28,36.83
  BOTTOM w1.016: UNK5V.1 93.98,60.01 84.14,60.01 79.69,55.56 66.99,55.56 64.14,58.42 49.53,58.42 44.13,53.02 P26.1
AGND: length 611.2
  TOP w0.203: 103.65,21.86 U1.5 101.56,21.86
  TOP w0.254: 139.72,45.15 139.62,45.05 ; v1(130.81,44.51) 130.81,44.55 ; 131.85,45.05 131.75,45.15 131.75,45.16 ; 131.97,44.46 131.97,44.45 ; 131.1,44.55 131.19,44.46
  TOP w0.305: P22.6 v1(140.01,43.25) ; P22.52 v1(140.01,15.65) ; v1(124.46,6.03) 124.2,6.29 U12.4 ; P22.75 131.65,19.25 v1(131.13,18.73) ; U1.5 v1(102.6,21.32) ; v1(73.66,79.38) 73.79,79.51 U6.2 76.02,79.51 v1(76.2,79.69) ; v1(140.02,45.34) 139.83,45.15 139.72,45.15 ; U10.4 118.09,69.24 118.11,69.26 118.11,69.85 ; U10.4 117.42,69.8 117.48,69.85 ; U10.4 116.58,69.24 116.24,69.57 ; 131.75,45.16 131.51,45.4 v1(130.81,45.4) ; P22.4 v1(140.01,44.45) ; U3.9 v1(65.22,29.87) ; 131.85,45.05 P22.118 ; v1(73.66,80.65) 73.79,80.51 U6.4 ; v1(140.02,18.73) 140.02,18.97 139.74,19.25 P22.46 ; P22.11 v1(140.01,40.25) ; 131.97,44.45 P22.117 ; 73.98,76.84 73.53,77.29 U6.19 ; v1(130.49,25.08) 131.26,25.85 P22.86 ; v1(125.75,7.9) 126,8.15 U12.7 127.92,8.15 ; P22.23 v1(140.01,33.05) ; P22.28 v1(140.01,30.05) ; v1(130.49,30.48) 130.92,30.05 P22.93 ; P22.104 v1(131.47,36.65) ; v1(131.13,42.55) 131.83,43.25 P22.115 ; P22.17 v1(140.01,36.65) ; U3.2 v1(65.22,27.92) ; P22.81 131.45,22.85 v1(131.13,23.18) ; P22.109 v1(131.47,39.65) ; 139.62,45.05 P22.3 ; U2.12 v1(45.97,33.53) ; P22.69 v1(131.47,15.65) ; P22.36 v1(140.01,25.25) ; v1(66.36,80.01) U6.13 v1(73.03,80.01) U6.8 ; P22.40 v1(140.01,22.85) ; v1(119.38,4.76) 119.5,4.89 R66.1 ; 131.19,44.46 131.97,44.46 ; P22.58 v1(140.01,12.05) ; U7.3 93.91,85.34 v1(93.66,85.09) 93.41,85.34 U7.6 ; P22.98 v1(131.47,33.05) ; 130.81,44.55 131.1,44.55 ; U5.9 75.84,22.36 75.84,22.36 76.1,22.36 76.32,22.14 76.45,22.14 v1(76.99,21.59) ; R64.1 v1(122.51,11.15) ; P22.63 v1(131.47,12.05)
  TOP w0.381: v1(125.73,33.34) 125.43,33.03 U16.3 ; U15.3 v1(125.6,26.68) ; U14.3 v1(125.4,20.96)
  TOP w0.508: S1.7G 20.26,33.02 ; 61.28,10.8 61.28,12.13 ; 61.28,10.8 59.94,10.8 ; 61.28,10.8 62.61,10.8 ; GND1.1 95.89,17.46 ; GND1.1 97.47,15.88 ; GND1.1 94.3,15.88 ; GND1.1 95.89,14.29 ; P25.9 4.45,13.4 ; P25.9 5.84,12.01 ; P25.9 4.45,10.61 ; P25.9 3.05,12.01 ; 4.45,43.63 P1.9 ; P1.9 3.05,45.03 ; P1.9 4.45,46.42 ; S1.2B 19.05,46.93 ; S1.2B 17.84,45.72 ; S1.2B 20.26,45.72 ; P20.1 37.8,87.5 ; P20.1 36.28,89.03 ; P20.1 36.28,85.98 ; P20.1 34.76,87.5 ; 19.05,47.05 S1.1A ; S1.1A 20.26,48.26 ; S1.1A 17.84,48.26 ; S1.1A 19.05,49.47 ; S1.3C 20.26,43.18 ; 49.21,10.8 49.21,12.13 ; 49.21,10.8 50.55,10.8 ; 49.21,10.8 47.88,10.8 ; 72.39,19.05 P24.2 73.66,20.32 ; GND4.1 22.86,5.71 ; GND4.1 19.68,5.71 ; GND4.1 21.27,7.3 ; GND4.1 21.27,4.13 ; 45.4,10.8 46.74,10.8 ; 45.4,10.8 45.4,12.13 ; 45.4,10.8 44.07,10.8 ; 86.36,46.04 P14.2 ; P14.2 85.09,47.31 ; P14.2 86.36,48.58 ; 107.19,90.17 108.59,90.17 ; 108.59,90.17 108.59,88.77 ; 108.59,90.17 108.59,91.57 ; 108.59,90.17 109.98,90.17 ; 120.65,54.29 GND2.1 ; GND2.1 122.24,55.88 ; GND2.1 120.65,57.47 ; GND2.1 119.06,55.88 ; GND3.1 49.21,68.58 ; GND3.1 47.63,66.99 ; GND3.1 46.04,68.58 ; GND3.1 47.63,70.17 ; P26.3 49.21,52.77 ; P26.3 49.21,50.1 ; P26.3 50.55,51.44 ; C6.1 v1(41.02,34.61) ; S1.8H 20.26,30.48 ; S1.8H 19.05,29.27 ; S1.8H 17.84,30.48 ; 51.69,10.8 53.02,10.8 ; 53.02,10.8 53.02,12.13 ; 53.02,10.8 54.36,10.8 ; S1.4D 20.26,40.64 ; 65.72,10.8 65.72,12.13 ; 65.72,10.8 64.39,10.8 ; 65.72,10.8 67.06,10.8 ; 73.22,50.68 P21.2 73.22,52.82 ; S1.5E 20.26,38.1 ; C7.1 v1(41.02,32.38) ; S1.6F 20.26,35.56
  TOP w0.635: C33.2 109.44,26.89 v1(109.54,26.99) ; C29.1 v1(90.81,18.73) ; R31.1 v1(84.14,30.8) ; R25.1 v1(80.33,47.94) ; R37.1 v1(74.61,90.49) ; C27.1 v1(80.33,31.43) ; C40.1 v1(97.16,43.18) ; U9.2 v1(104.78,33.66) ; C59.1 v1(125.79,17.14) ; C8.1 v1(41.02,30.16) ; C34.1 v1(98.11,56.52) ; C58.1 v1(125.79,29.84) ; U11.2 90.49,63.82 89.95,63.29 C56.1 ; POWER.C v1(31.75,76.2) ; C56.1 v1(89.95,62.33) ; C56.1 v1(88.9,63.18) ; C36.1 v1(66.36,78.74) ; C32.1 v1(100.33,26.35) ; C3.1 v1(41.02,41.27) ; C2.1 v1(41.02,43.5) ; C16.1 v1(41.02,12.38) ; C48.2 67.31,80.96 v1(66.37,80.96) ; C19.1 v1(62.39,33.81) ; v1(89.95,71.34) C54.1 v1(88.9,70.48) ; C4.1 v1(41.02,39.05) ; C5.1 v1(41.02,36.83) ; R30.2 v1(99.7,18.1) ; 77.15,84.46 v1(77.15,83.82) ; C11.1 v1(41.02,23.49) ; C15.1 v1(41.02,14.61) ; C10.1 v1(41.02,25.72) ; C26.1 v1(77.15,28.1) ; C12.1 v1(41.02,21.27) ; C13.1 v1(41.02,19.05) ; C31.1 105.54,27.75 v1(105.73,27.94) ; C23.2 v1(62.55,24.13) ; R38.1 v1(73.03,90.49) ; C39.1 v1(97.16,45.72) ; C45.2 v1(98.11,35.56) ; U13.3 v1(126.19,40.32) ; C21.2 v1(87.79,34.92) ; C14.1 v1(41.02,16.83) ; RN1.6 v1(80.33,39.05) ; C9.1 v1(41.02,27.94) ; R44.1 v1(79.06,82.55) ; C1.1 v1(41.02,45.72) ; 72.07,84.46 v1(72.07,83.82) ; C18.2 v1(55.94,34.61) ; C17.2 v1(56.26,23.81) ; C22.2 v1(62.55,21.59) ; U8.4 v1(98.74,52.07) ; C60.1 v1(125.79,36.2) ; C20.1 v1(62.39,36.2) ; C24.1 v1(68.1,27.62) ; C42.1 v1(103.19,40.64) ; C61.1 v1(125.79,23.49) ; C35.1 v1(61.28,74.61)
  TOP w1.27: P19.2 v1(49.8,89.27) ; P19.2 v1(47.84,91.76) ; P19.2 v1(46.09,89.27) ; P19.2 v1(47.84,86.78)
  L2_GND w0.508: 17.84,38.1 S1.5E ; S1.5E 19.05,36.89 ; S1.5E 20.26,38.1 ; S1.5E 19.05,39.31 ; 49.21,10.8 49.21,12.13 ; 49.21,10.8 50.55,10.8 ; 49.21,10.8 47.88,10.8 ; 19.05,31.81 S1.7G ; S1.7G 19.05,34.23 ; S1.7G 17.84,33.02 ; S1.7G 20.26,33.02 ; P1.9 5.84,45.03 ; P1.9 4.45,46.42 ; P1.9 3.05,45.03 ; P1.9 4.45,43.63 ; 45.4,10.8 45.4,12.13 ; 45.4,10.8 46.74,10.8 ; 45.4,10.8 44.07,10.8 ; GND1.1 95.89,17.46 ; GND1.1 97.47,15.88 ; GND1.1 95.89,14.29 ; GND1.1 94.3,15.88 ; 46.04,68.58 GND3.1 ; GND3.1 47.63,70.17 ; GND3.1 47.63,66.99 ; GND3.1 49.21,68.58 ; P20.1 37.8,87.5 ; P20.1 36.28,89.03 ; P20.1 34.76,87.5 ; P20.1 36.28,85.98 ; P26.3 50.55,51.44 ; P26.3 49.21,52.77 ; P26.3 49.21,50.1 ; 107.19,90.17 108.59,90.17 ; 108.59,90.17 109.98,90.17 ; 108.59,90.17 108.59,91.57 ; 108.59,90.17 108.59,88.77 ; 85.09,47.31 P14.2 ; P14.2 86.36,46.04 ; P14.2 86.36,48.58 ; S1.2B 20.26,45.72 ; S1.2B 17.84,45.72 ; S1.2B 19.05,44.51 ; S1.2B 19.05,46.93 ; 119.06,55.88 GND2.1 ; GND2.1 120.65,54.29 ; GND2.1 122.24,55.88 ; GND2.1 120.65,57.47 ; 72.39,19.05 P24.2 ; P24.2 71.12,20.32 ; P24.2 73.66,20.32 ; S1.8H 19.05,31.69 ; S1.8H 20.26,30.48 ; S1.8H 17.84,30.48 ; S1.8H 19.05,29.27 ; 61.28,10.8 61.28,12.13 ; 61.28,10.8 59.94,10.8 ; 61.28,10.8 62.61,10.8 ; 53.02,10.8 53.02,12.13 ; 53.02,10.8 51.69,10.8 ; 53.02,10.8 54.36,10.8 ; S1.3C 20.26,43.18 ; S1.3C 19.05,41.97 ; S1.3C 19.05,44.39 ; S1.3C 17.84,43.18 ; P21.2 75.37,50.68 ; P21.2 73.22,52.82 ; P21.2 73.22,50.68 ; P21.2 75.37,52.82 ; 21.27,4.13 GND4.1 ; GND4.1 21.27,7.3 ; GND4.1 19.68,5.71 ; GND4.1 22.86,5.71 ; 17.84,40.64 S1.4D ; S1.4D 19.05,41.85 ; S1.4D 20.26,40.64 ; S1.4D 19.05,39.43 ; 65.72,10.8 65.72,12.13 ; 65.72,10.8 67.06,10.8 ; 65.72,10.8 64.39,10.8 ; 4.45,10.61 P25.9 ; P25.9 5.84,12.01 ; P25.9 4.45,13.4 ; P25.9 3.05,12.01 ; 19.05,47.05 S1.1A ; S1.1A 19.05,49.47 ; S1.1A 20.26,48.26 ; S1.1A 17.84,48.26 ; S1.6F 20.26,35.56 ; S1.6F 17.84,35.56 ; S1.6F 19.05,34.35 ; S1.6F 19.05,36.77
  L3_POWER w0.508: S1.1A 19.05,49.47 ; S1.1A 20.26,48.26 ; S1.1A 19.05,47.05 ; S1.1A 17.84,48.26 ; 19.05,31.81 S1.7G ; S1.7G 19.05,34.23 ; S1.7G 20.26,33.02 ; S1.7G 17.84,33.02 ; 19.05,41.97 S1.3C ; S1.3C 17.84,43.18 ; S1.3C 19.05,44.39 ; S1.3C 20.26,43.18 ; S1.6F 19.05,36.77 ; S1.6F 20.26,35.56 ; S1.6F 19.05,34.35 ; S1.6F 17.84,35.56 ; 3.05,45.03 P1.9 ; P1.9 4.45,46.42 ; P1.9 5.84,45.03 ; P1.9 4.45,43.63 ; P25.9 5.84,12.01 ; P25.9 3.05,12.01 ; P25.9 4.45,13.4 ; P25.9 4.45,10.61 ; 47.63,66.99 GND3.1 ; GND3.1 49.21,68.58 ; GND3.1 47.63,70.17 ; GND3.1 46.04,68.58 ; 59.94,10.8 61.28,10.8 ; 61.28,10.8 61.28,12.13 ; 61.28,10.8 62.61,10.8 ; 19.05,36.89 S1.5E ; S1.5E 19.05,39.31 ; S1.5E 17.84,38.1 ; S1.5E 20.26,38.1 ; 19.05,39.43 S1.4D ; S1.4D 17.84,40.64 ; S1.4D 19.05,41.85 ; S1.4D 20.26,40.64 ; P26.3 50.55,51.44 ; P26.3 49.21,50.1 ; P26.3 49.21,52.77 ; 72.39,19.05 P24.2 ; P24.2 71.12,20.32 ; P24.2 73.66,20.32 ; 34.76,87.5 P20.1 ; P20.1 37.8,87.5 ; P20.1 36.28,85.98 ; P20.1 36.28,89.03 ; 19.05,29.27 S1.8H ; S1.8H 19.05,31.69 ; S1.8H 17.84,30.48 ; S1.8H 20.26,30.48 ; 65.72,10.8 65.72,12.13 ; 65.72,10.8 64.39,10.8 ; 65.72,10.8 67.06,10.8 ; 45.4,10.8 45.4,12.13 ; 45.4,10.8 46.74,10.8 ; 45.4,10.8 44.07,10.8 ; S1.2B 20.26,45.72 ; S1.2B 17.84,45.72 ; S1.2B 19.05,44.51 ; S1.2B 19.05,46.93 ; 53.02,10.8 53.02,12.13 ; 53.02,10.8 51.69,10.8 ; 53.02,10.8 54.36,10.8 ; 107.19,90.17 108.59,90.17 ; 108.59,90.17 108.59,88.77 ; 108.59,90.17 109.98,90.17 ; 108.59,90.17 108.59,91.57 ; 21.27,4.13 GND4.1 ; GND4.1 19.68,5.71 ; GND4.1 22.86,5.71 ; GND4.1 21.27,7.3 ; 49.21,10.8 49.21,12.13 ; 49.21,10.8 47.88,10.8 ; 49.21,10.8 50.55,10.8 ; 85.09,47.31 P14.2 ; P14.2 86.36,48.58 ; P14.2 86.36,46.04 ; 75.37,52.82 P21.2 75.37,50.68 ; 120.65,57.47 GND2.1 122.24,55.88 ; 95.89,14.29 GND1.1 ; GND1.1 94.3,15.88 ; GND1.1 95.89,17.46 ; GND1.1 97.47,15.88
  BOTTOM w0.508: 108.59,88.77 108.59,90.17 ; 108.59,90.17 107.19,90.17 ; 108.59,90.17 108.59,91.57 ; 108.59,90.17 109.98,90.17 ; 4.45,43.63 P1.9 ; P1.9 4.45,46.42 ; P1.9 3.05,45.03 ; P1.9 5.84,45.03 ; 44.07,10.8 45.4,10.8 ; 45.4,10.8 45.4,12.13 ; 45.4,10.8 46.74,10.8 ; 47.63,66.99 GND3.1 ; GND3.1 49.21,68.58 ; GND3.1 47.63,70.17 ; GND3.1 46.04,68.58 ; S1.6F 20.26,35.56 ; S1.6F 19.05,34.35 ; S1.6F 19.05,36.77 ; S1.6F 17.84,35.56 ; 85.09,47.31 P14.2 ; P14.2 86.36,46.04 ; P14.2 86.36,48.58 ; GND1.1 95.89,17.46 ; GND1.1 97.47,15.88 ; GND1.1 94.3,15.88 ; GND1.1 95.89,14.29 ; 119.06,55.88 GND2.1 ; GND2.1 120.65,57.47 ; GND2.1 122.24,55.88 ; GND2.1 120.65,54.29 ; 50.55,10.8 49.21,10.8 49.21,12.13 ; S1.5E 20.26,38.1 ; S1.5E 19.05,36.89 ; S1.5E 17.84,38.1 ; S1.5E 19.05,39.31 ; 71.12,20.32 P24.2 ; P24.2 73.66,20.32 ; P24.2 72.39,19.05 ; S1.1A 20.26,48.26 ; S1.1A 19.05,47.05 ; S1.1A 17.84,48.26 ; S1.1A 19.05,49.47 ; P25.9 4.45,13.4 ; P25.9 5.84,12.01 ; P25.9 4.45,10.61 ; P25.9 3.05,12.01 ; 17.84,43.18 S1.3C ; S1.3C 19.05,41.97 ; S1.3C 19.05,44.39 ; S1.3C 20.26,43.18 ; S1.8H 20.26,30.48 ; S1.8H 19.05,29.27 ; S1.8H 19.05,31.69 ; S1.8H 17.84,30.48 ; 19.68,5.71 GND4.1 ; GND4.1 21.27,7.3 ; GND4.1 22.86,5.71 ; GND4.1 21.27,4.13 ; 61.28,10.8 61.28,12.13 ; 61.28,10.8 59.94,10.8 ; 61.28,10.8 62.61,10.8 ; S1.7G 19.05,34.23 ; S1.7G 19.05,31.81 ; S1.7G 20.26,33.02 ; S1.7G 17.84,33.02 ; S1.2B 20.26,45.72 ; S1.2B 19.05,46.93 ; S1.2B 19.05,44.51 ; S1.2B 17.84,45.72 ; 65.72,10.8 65.72,12.13 ; 65.72,10.8 64.39,10.8 ; 65.72,10.8 67.06,10.8 ; 17.84,40.64 S1.4D ; S1.4D 19.05,41.85 ; S1.4D 20.26,40.64 ; S1.4D 19.05,39.43 ; 34.76,87.5 P20.1 ; P20.1 36.28,85.98 ; P20.1 36.28,89.03 ; P20.1 37.8,87.5 ; P26.3 50.55,51.44 ; P26.3 49.21,52.77 ; P26.3 49.21,50.1 ; 54.36,10.8 53.02,10.8 53.02,12.13
  vias: v1(13.97,45.72) v1(13.97,43.18) v1(13.97,40.64) v1(13.97,38.1) v1(13.97,35.56) v1(13.97,33.02) v1(13.97,30.48) v1(20.64,24.45) v1(20.64,22.54) v1(20.64,20) v1(20.64,17.78) v1(20.64,15.56) v1(20.64,13.65) v1(30.48,76.2) v1(32.39,44.61) v1(32.39,42.39) v1(32.39,40.16) v1(32.39,37.78) v1(32.39,35.72) v1(32.39,33.5) v1(32.39,31.27) v1(32.39,29.05) v1(32.39,26.99) v1(32.39,24.45) v1(32.39,22.22) v1(32.39,20) v1(32.39,18.1) v1(32.39,15.56) v1(32.39,13.49) v1(32.54,46.99) v1(41.75,7.62) v1(50.32,3.65) v1(50.48,14.92) v1(54.77,4.13) v1(57.47,8.25) v1(64.14,88.11) v1(66.2,90.33) v1(66.99,86.2) v1(67.95,14.76) v1(68.58,87.79) v1(70.17,8.57) v1(72.39,80.65) v1(72.39,79.38) v1(72.71,62.87) v1(72.71,61.59) v1(72.71,59.05) v1(72.71,57.78) v1(72.71,31.11) v1(72.71,29.21) v1(73.34,66.99) v1(73.34,66.04) v1(73.66,63.82) v1(73.66,62.23) v1(73.66,60.64) v1(73.66,58.42) v1(73.66,56.83) v1(74.3,2.22) v1(74.61,62.87) v1(74.61,61.59) v1(74.61,59.05) v1(74.61,57.78) v1(74.61,20.95) v1(75.25,82.07) v1(75.41,10.64) v1(75.57,76.2) v1(75.57,75.25) v1(75.57,74.3) v1(76.61,22.66) v1(76.84,5.08) v1(82.87,10.64) v1(83.5,5.08) v1(86.68,22.54) v1(88.27,52.7) v1(90.81,26.67) v1(92.08,80.01) v1(93.03,80.01) v1(93.35,82.55) v1(93.35,81.6) v1(93.66,86.04) v1(93.66,84.14) v1(93.98,80.01) v1(93.98,22.86) v1(94.3,88.27) v1(94.3,87.31) v1(94.93,80.01) v1(99.7,12.07) v1(99.7,9.84) v1(99.7,7.62) v1(99.7,5.4) v1(99.7,3.17) v1(109.22,6.35) v1(109.54,10.8) v1(109.86,32.38) v1(109.86,29.69) v1(110.17,20) v1(112.08,8.89) v1(112.4,3.97) v1(113.67,65.72) v1(114.3,73.03) v1(114.94,65.72) v1(115.25,73.03) v1(115.25,72.07) v1(115.25,70.8) v1(115.25,69.22) v1(115.25,68.26) v1(115.25,67.31) v1(116.21,73.03) v1(116.21,65.72) v1(117.48,22.22) v1(125.73,8.89) v1(125.73,6.99)
P15VA: length 15.6
  TOP w0.508: P21.1 78.17,51.75 ; P21.1 76.84,53.09 ; P21.1 76.84,50.42
  BOTTOM w0.508: P13.1 66.52,43.81 ; P13.1 63.98,43.81 ; P13.1 65.25,45.09 ; 76.84,50.42 P21.1 ; P21.1 78.17,51.75 ; P21.1 76.84,53.09 ; 52.07,43.81 P8.1 ; P8.1 53.34,45.09 ; P8.1 54.61,43.81
VIN: length 29.1
  TOP w0.508: 46.04,76.2 VIN.1 ; VIN.1 49.21,76.2 ; VIN.1 47.63,74.61 ; VIN.1 47.63,77.79 ; 39.76,87.5 P20.2 ; P20.2 41.28,85.98 ; P20.2 41.28,89.03 ; P20.2 42.8,87.5
  TOP w0.635: P19.1 59.26,91.33 59.37,91.44 ; P19.1 61.23,89.27 61.28,89.22 ; P19.1 56.57,89.27 56.52,89.22 ; P19.1 59.26,87.2 59.06,87
  TOP w0.762: v2(59.26,83.17) 59.26,85.07 ; v2(59.26,83.17) 60.97,83.17 ; v2(59.26,83.17) 59.26,81.26 ; v2(59.26,83.17) 57.54,83.17
3P3V: length 48.8
  TOP w0.381: v1(125.57,18.57) 125.11,19.04 U14.1 ; U15.5 122.54,25.39 122.24,25.08 v1(122.14,25.08) ; v1(125.51,25.08) 125.41,25.08 125.11,25.39 U15.1
  TOP w0.508: P18.1 113.98,36.89 ; P18.1 112.65,35.56 ; P18.1 113.98,34.23 ; 112.71,55.88 UNK3.3V.1 ; UNK3.3V.1 114.3,54.29 ; UNK3.3V.1 114.3,57.47 ; UNK3.3V.1 115.89,55.88 ; P17.1 110.81,38.1 ; P17.1 109.54,39.37 ; P17.1 108.27,38.1
  TOP w0.635: C59.2 v1(121.86,17.14) ; C61.2 v1(121.86,23.49) ; C58.2 v1(121.86,29.84) ; U14.5 v1(122.05,19.04) ; C60.2 v1(121.86,36.2) ; U16.5 v1(122.05,31.74) ; U13.5 v1(121.46,38.42)
  L3_POWER w0.508: 45.4,4.38 P4.1 ; P4.1 46.74,5.71 ; P4.1 44.07,5.71 ; P9.1 62.61,5.71 ; P9.1 61.28,4.38 ; P9.1 59.94,5.71 ; 49.21,4.38 P5.1 ; P5.1 50.55,5.71 ; P5.1 47.88,5.71 ; 53.02,4.38 P6.1 ; P6.1 51.69,5.71 ; P6.1 54.36,5.71 ; 114.3,54.29 UNK3.3V.1 ; UNK3.3V.1 114.3,57.47 ; UNK3.3V.1 115.89,55.88 ; 64.39,5.71 P10.1 ; P10.1 65.72,4.38 ; P10.1 67.06,5.71
AMP_ADDR0: length 64.6
  TOP w0.305: U3.4 66.22,25.81 v1(66.89,25.14)
  TOP w0.381: R22.1 R73.2 102.24,12.76 101.82,13.18 91.44,13.18 88.11,9.84 PGIA_0.1 78.11,9.84 75.57,12.38 69.85,12.38 P10.2
  BOTTOM w0.305: v1(66.89,25.14) 67.79,24.24 67.79,16.19 66.99,15.4 66.99,13.34 67.95,12.38 67.95,10.48 P10.2
AMP_ADDR1: length 67.2
  TOP w0.305: v1(67.63,26.04) 67.03,26.04 66.72,26.34 U3.5
  TOP w0.381: P9.2 62.55,6.99 66.99,6.99 69.85,9.84 PGIA_1.1 74.3,9.84 75.88,8.25 89.54,8.25 92.23,10.95 101.82,10.95 102.24,10.54 R72.2 R21.1
  BOTTOM w0.305: PGIA_1.1 72.39,13.65 68.9,17.14 68.9,24.77 v1(67.63,26.04)
BUFF_IN: length 13.4
  TOP w1.016: R28.1 C24.2 R26.2 70.7,32.07 70.17,32.6 DRV_IN.1 71.86,34.29 72.59,35.03 R20.1
CNV: length 49.7
  TOP w0.305: v1(126.68,39.05) 126.37,39.05 126.05,39.37 U13.2 ; U1.6 108,21.86 108.59,21.27 108.59,20.32 CNV.1 120.02,22.86 120.02,24.77 121.29,26.04 U15.2 125.23,26.04 125.3,25.96 126.29,25.96 v1(127,26.67) 127,27.39 127.26,27.65 P22.89
  BOTTOM w0.305: v1(126.68,39.05) 126.68,30.8 127,30.48 v1(127,26.67)
GPIO1: length 31.8
  TOP w0.305: P22.78 128.68,21.05 127,19.37 127,16.83 126.05,15.88 117.48,15.88 113.67,12.07 R22.2
